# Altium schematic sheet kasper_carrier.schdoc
size 821 x 574 mm; Device: default841x594; Symbol: default841x594; Name: default841x594; Size: "A1"; Id: /; File: kasper_carrier; Sheet: /
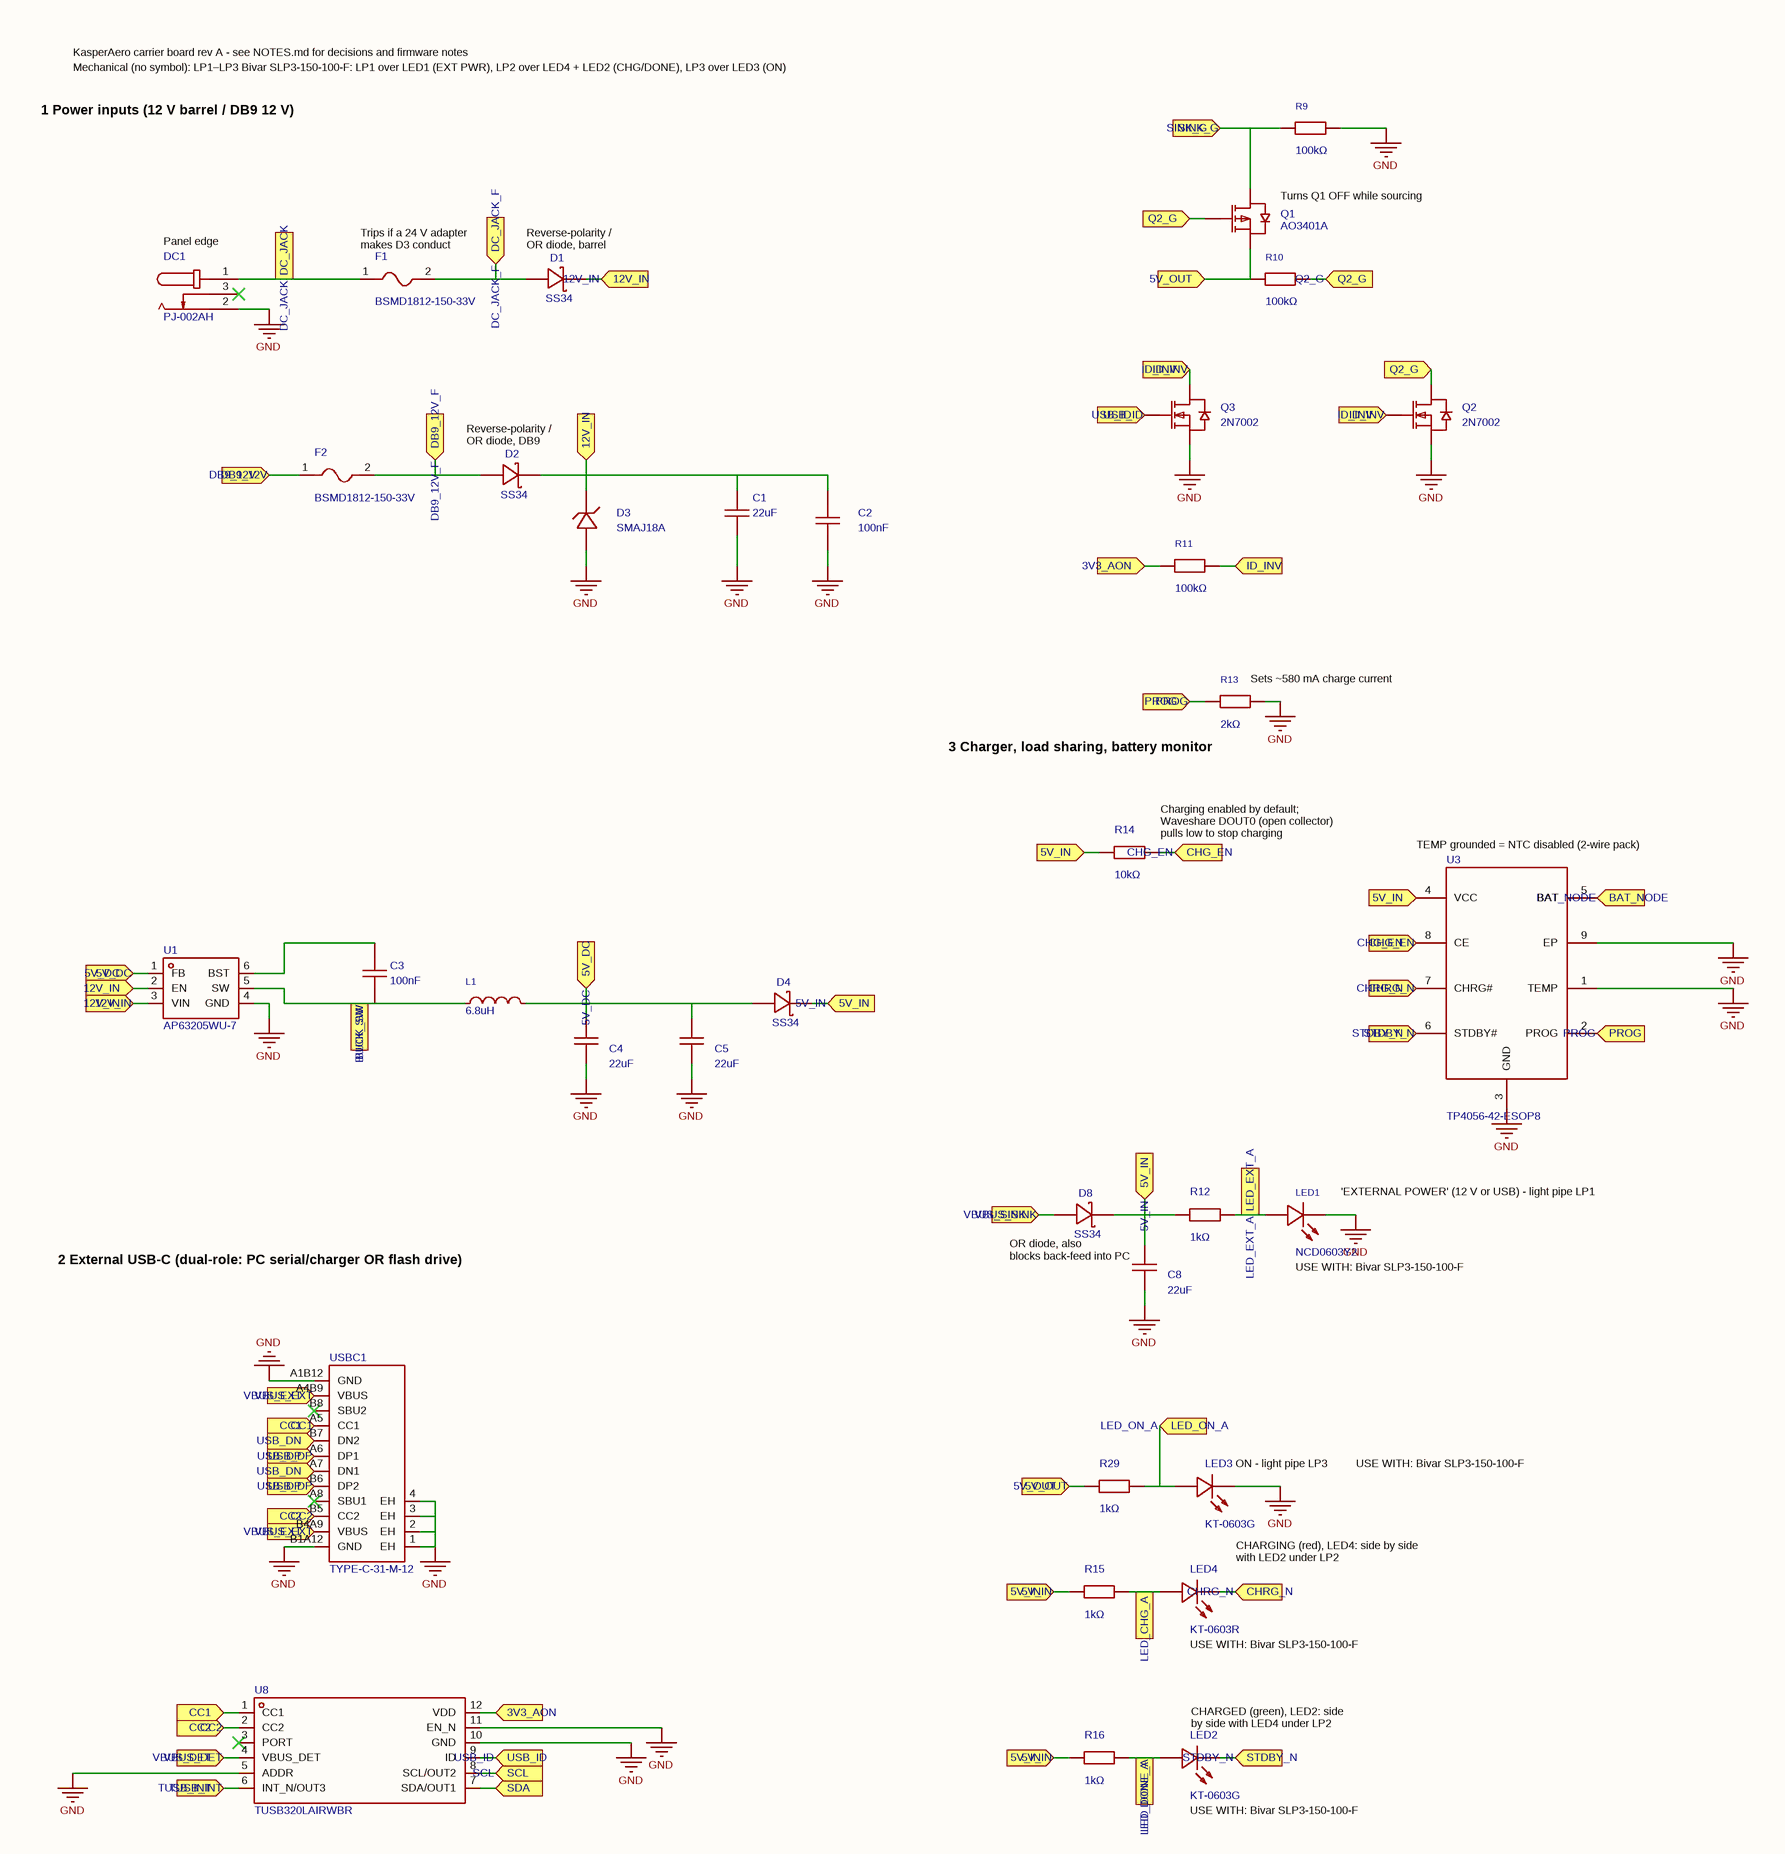
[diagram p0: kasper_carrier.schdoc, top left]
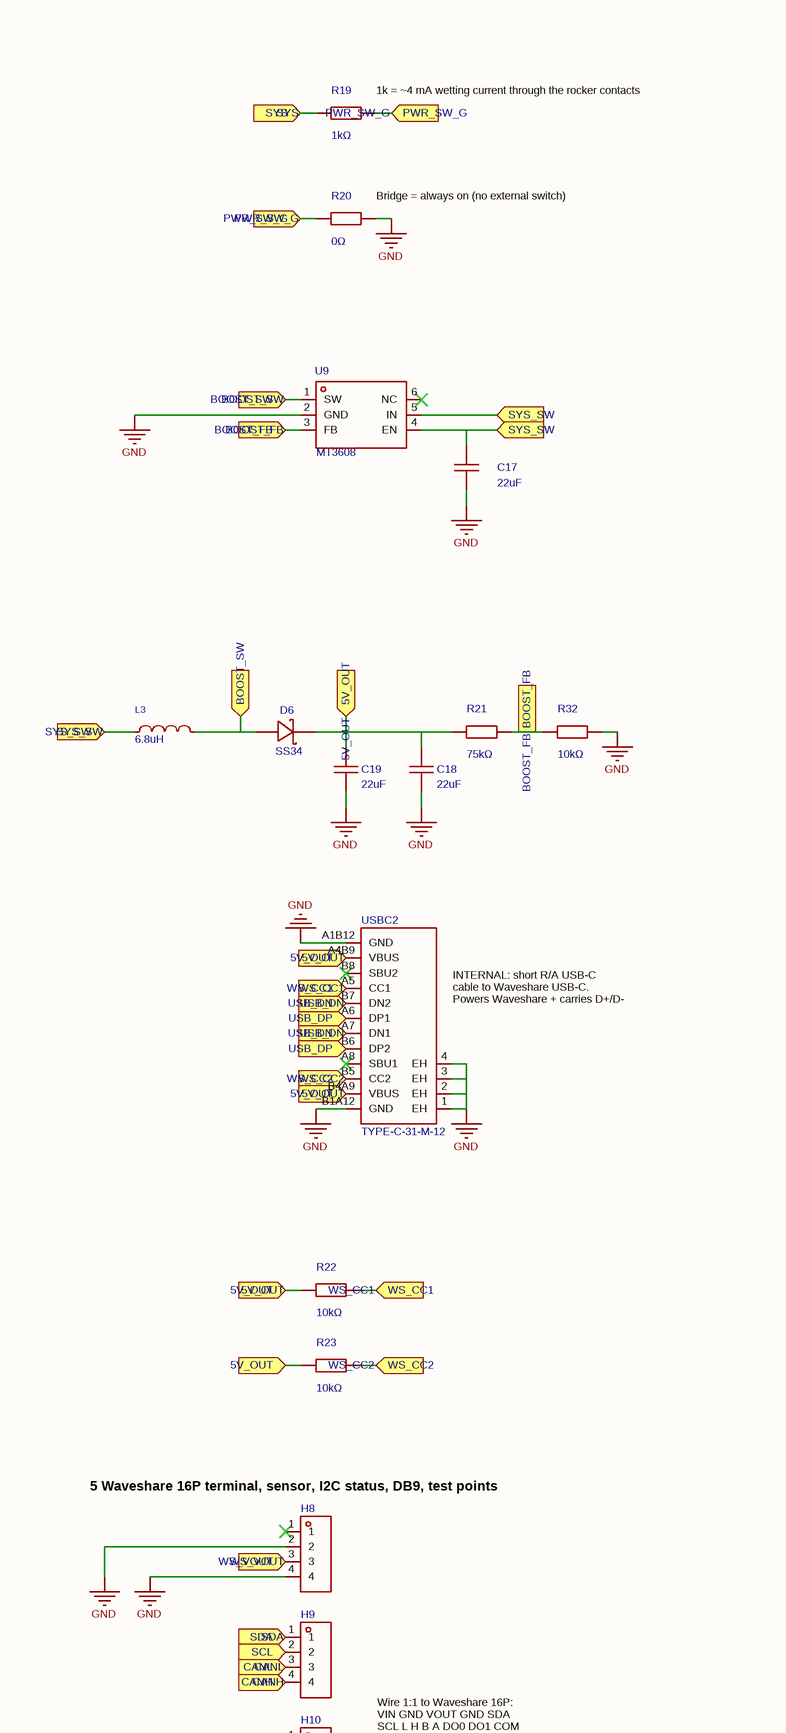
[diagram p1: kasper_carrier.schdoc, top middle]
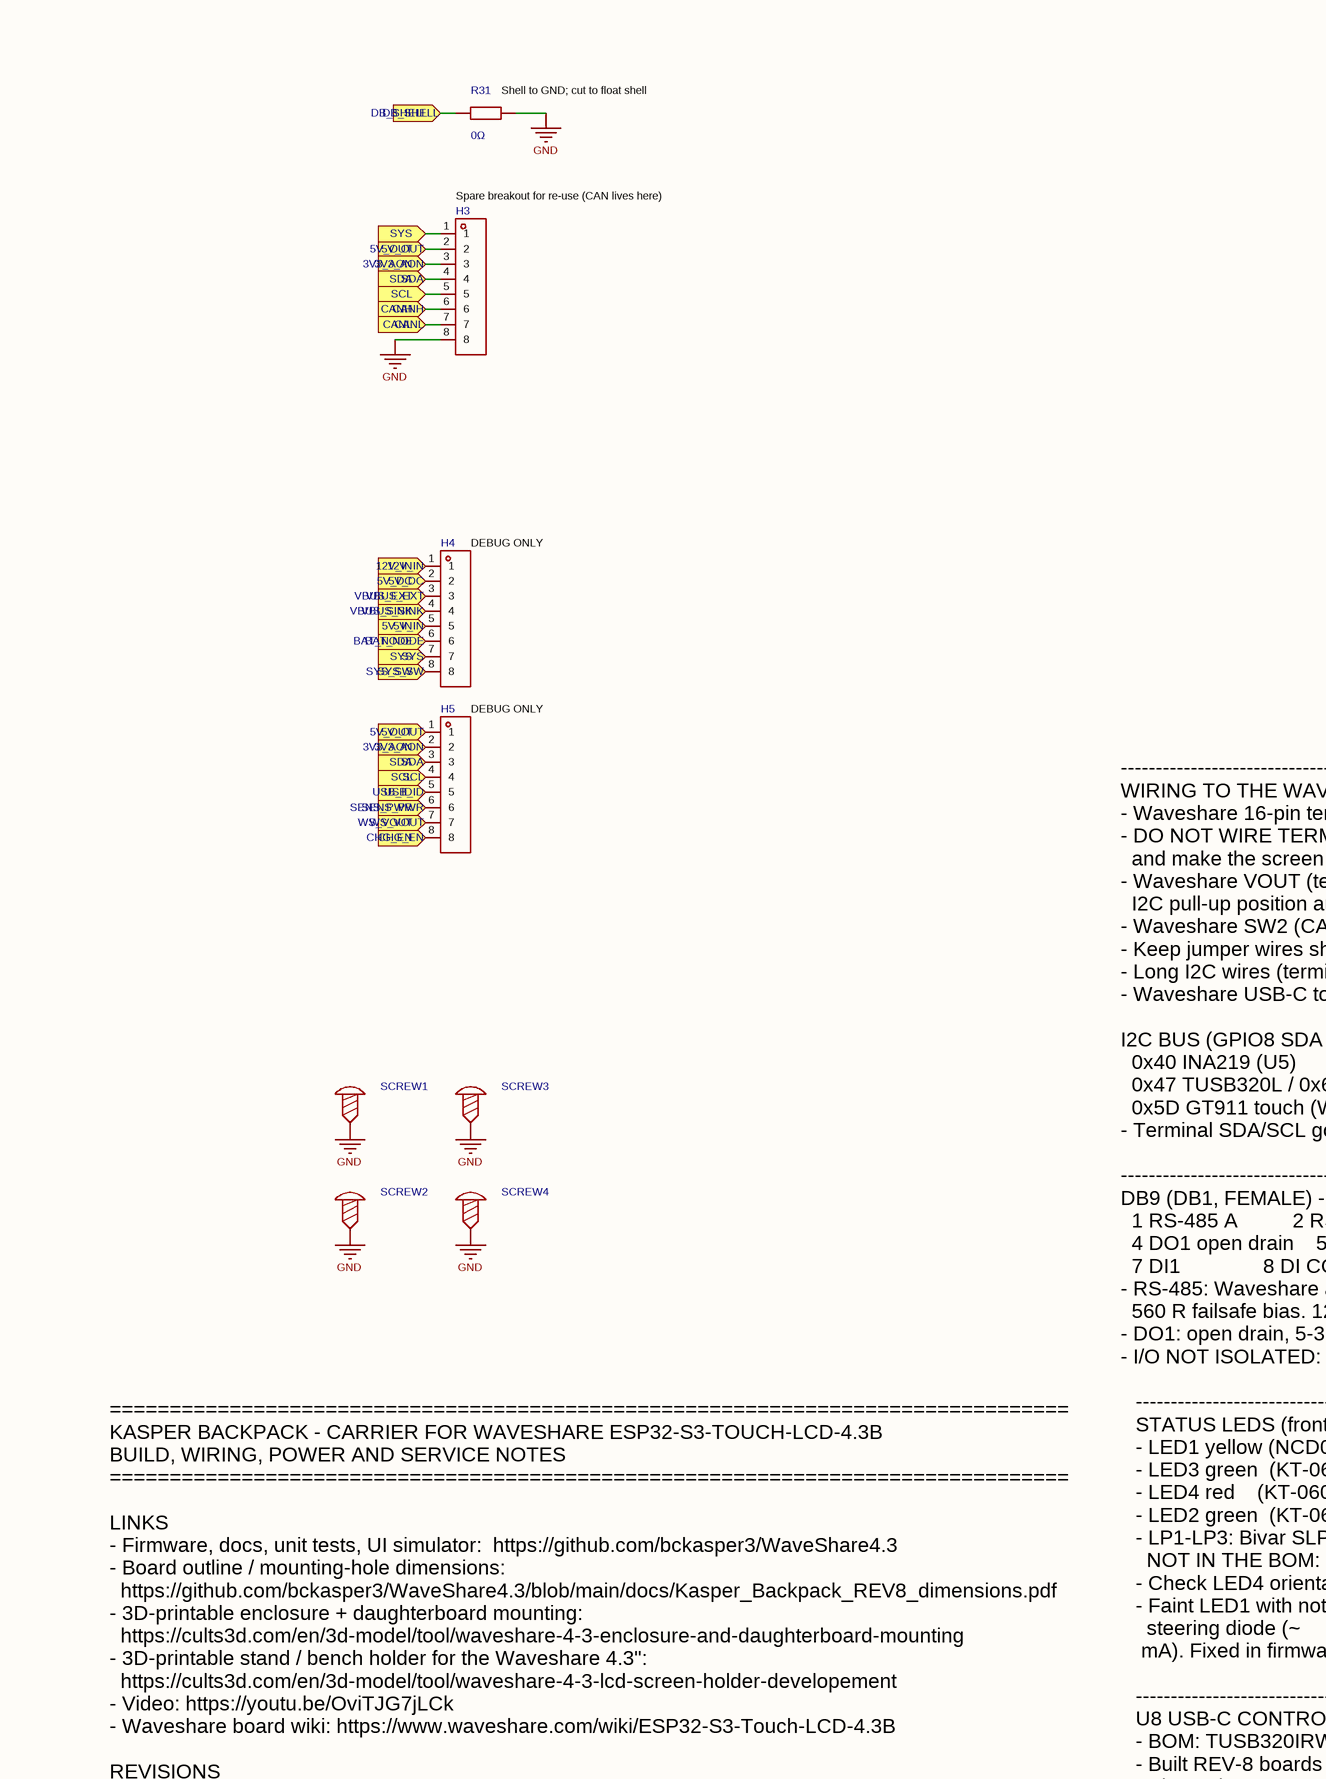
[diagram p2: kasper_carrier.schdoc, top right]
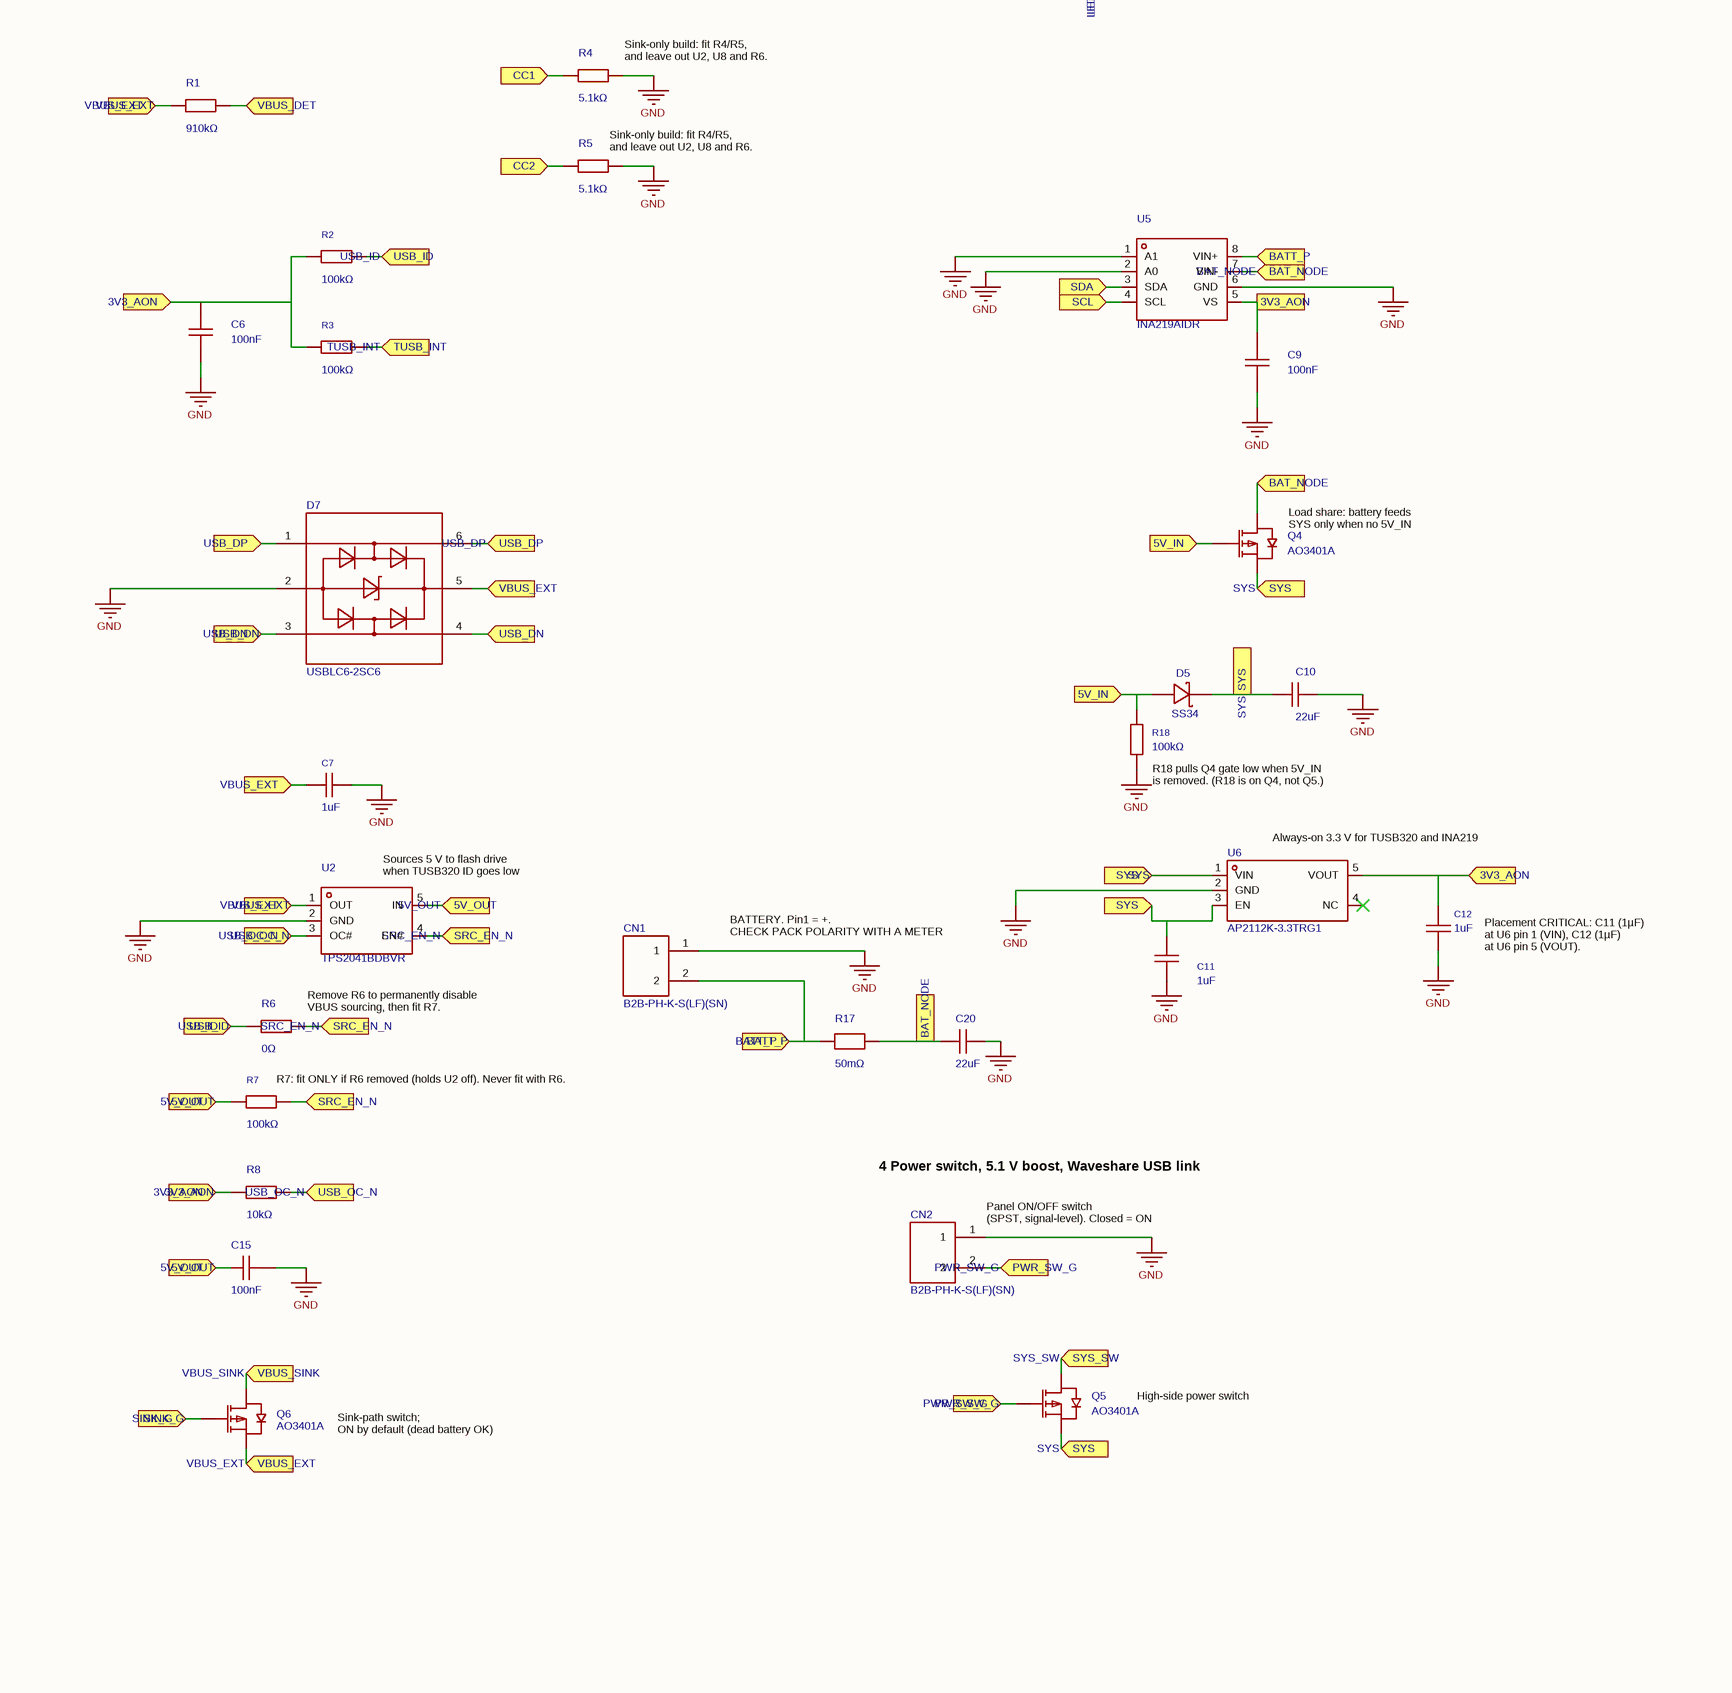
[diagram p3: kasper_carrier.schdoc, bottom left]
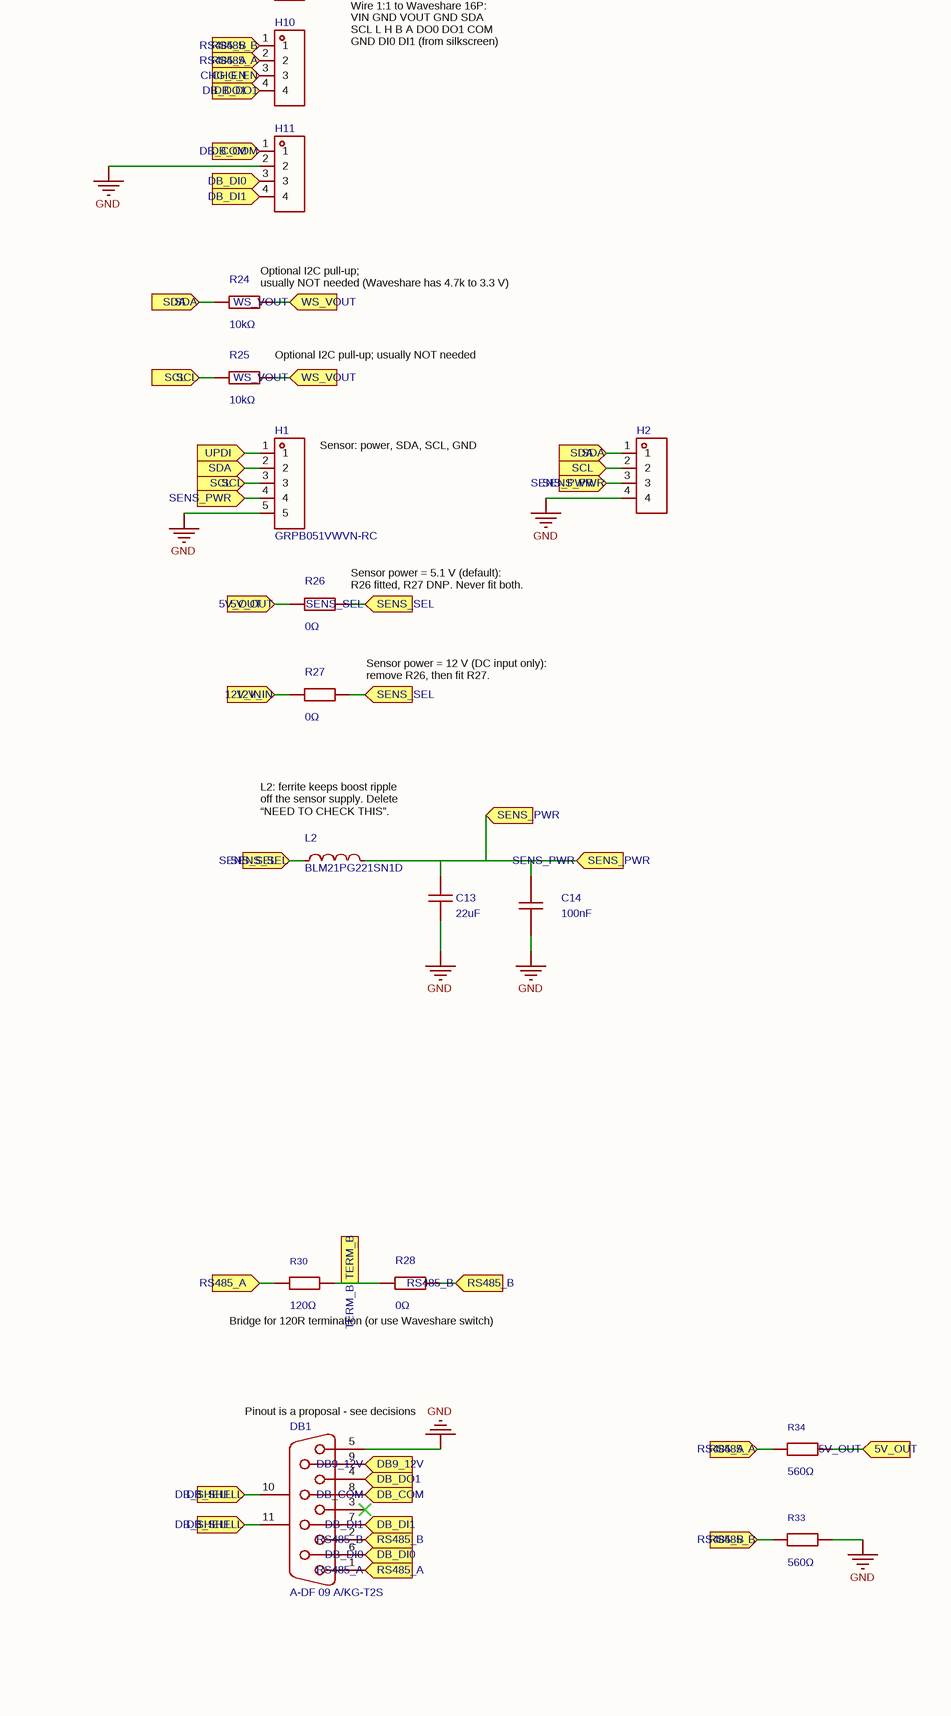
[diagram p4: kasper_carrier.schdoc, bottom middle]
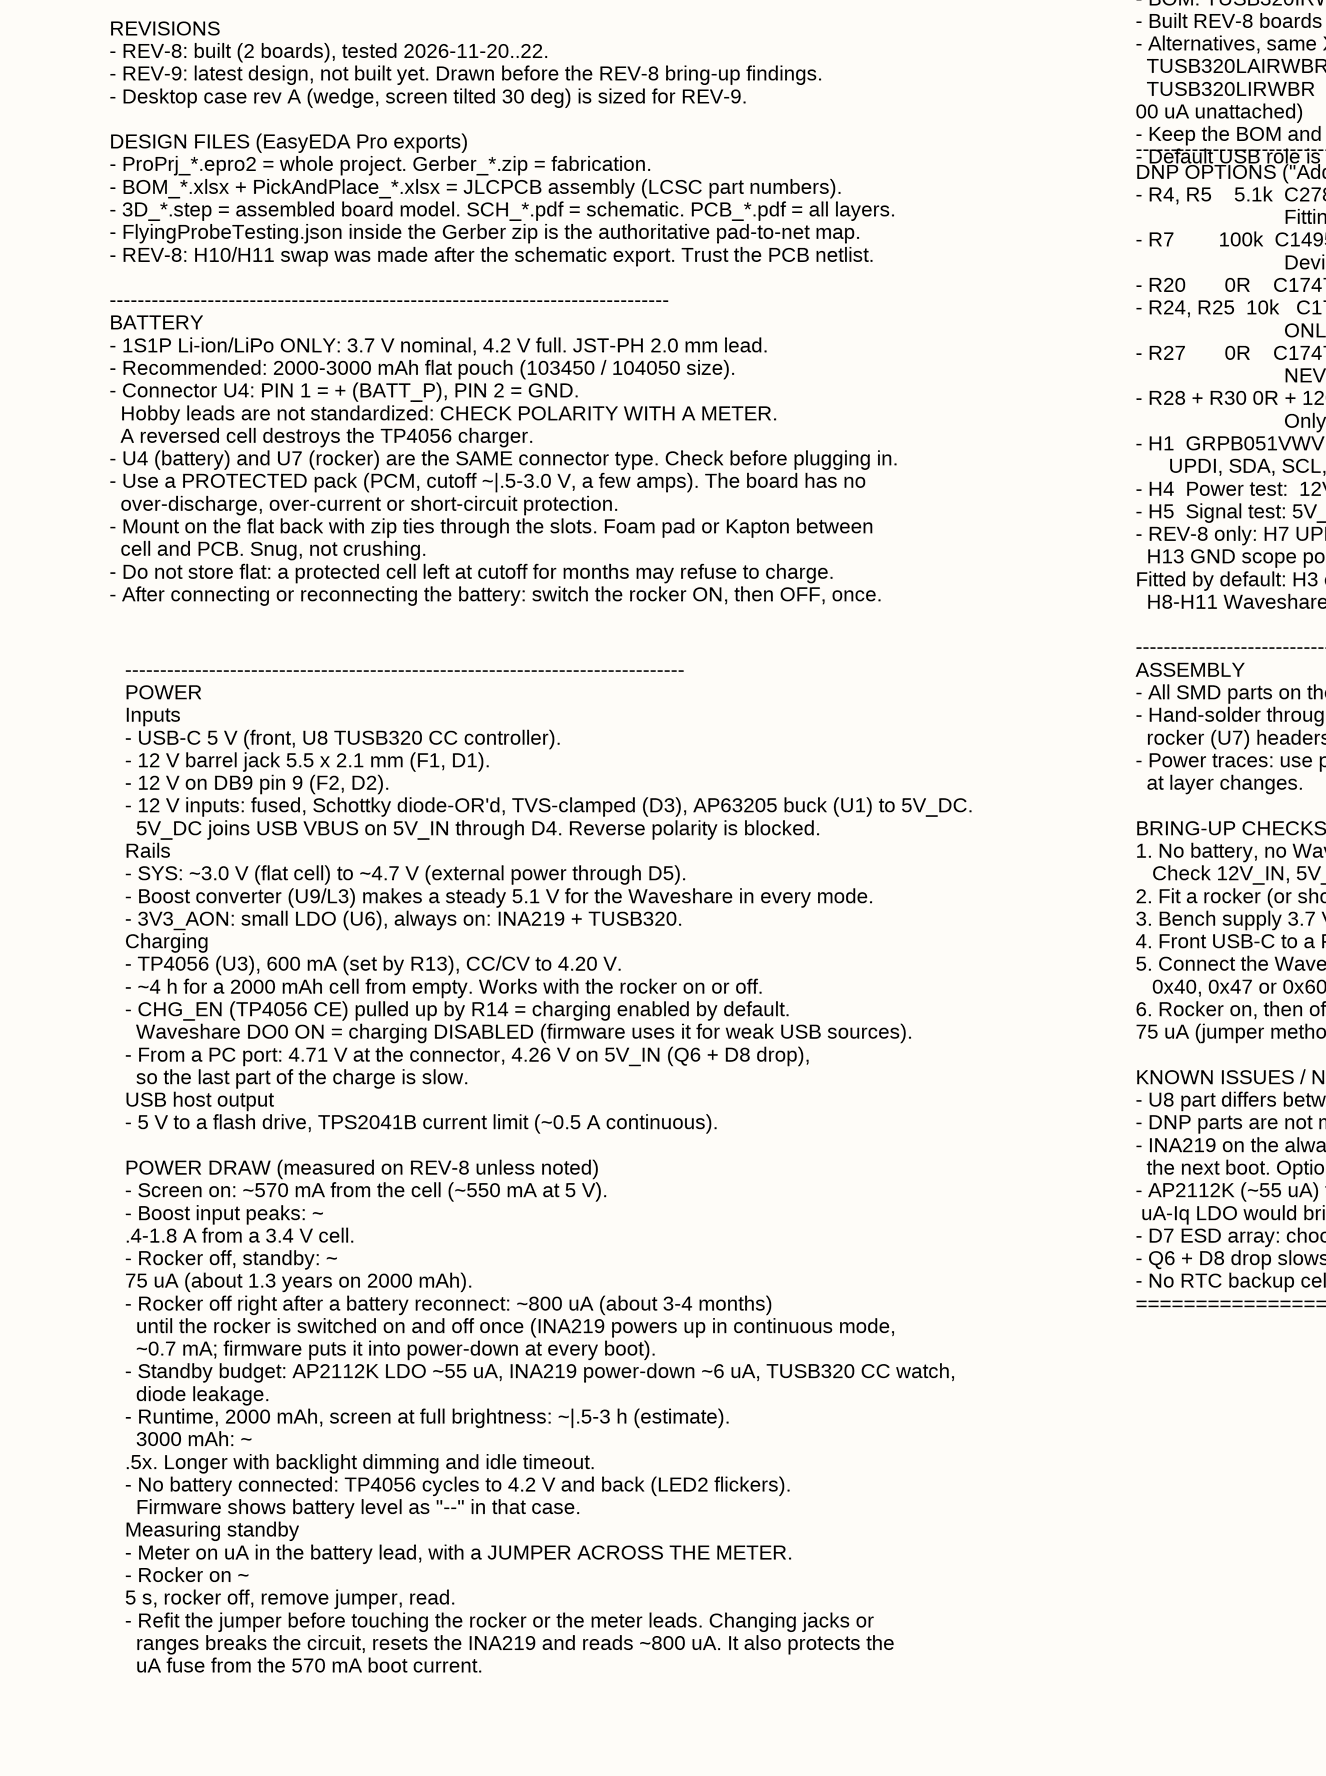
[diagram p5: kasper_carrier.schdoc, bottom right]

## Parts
C1  22uF  [C1206]
C2  100nF  [C0805]
C3  100nF  [C0805]
C4  22uF  [C1206]
C5  22uF  [C1206]
C6  100nF  [C0805]
C7  1uF  [C0805]
C8  22uF  [C1206]
C9  100nF  [C0805]
C10  22uF  [C1206]
C11  1uF  [C0805]
C12  1uF  [C0805]
C13  22uF  [C1206]
C14  100nF  [C0805]
C15  100nF  [C0805]
C17  22uF  [C1206]
C18  22uF  [C1206]
C19  22uF  [C1206]
C20  22uF  [C1206]
CN1  B2B-PH-K-S(LF)(SN)  [CONN-TH_B2B-PH-K-S]
CN2  B2B-PH-K-S(LF)(SN)  [CONN-TH_B2B-PH-K-S]
D1  SS34  [SMA_L4.3-W2.6-LS5.2-RD]
D2  SS34  [SMA_L4.3-W2.6-LS5.2-RD]
D3  SMAJ18A  [SMA_L4.4-W2.6-LS5.0-RD]
D4  SS34  [SMA_L4.3-W2.6-LS5.2-RD]
D5  SS34  [SMA_L4.3-W2.6-LS5.2-RD]
D6  SS34  [SMA_L4.3-W2.6-LS5.2-RD]
D7  USBLC6-2SC6  [SOT-23-6_L2.9-W1.6-P0.95-LS2.8-BL]
D8  SS34  [SMA_L4.3-W2.6-LS5.2-RD]
DB1  A-DF 09 A/KG-T2S  [DB9-TH_DB9F_C9900018961]
DC1  PJ-002AH  [DC-IN-TH_PJ-002AH]
F1  BSMD1812-150-33V  [F1812]
F2  BSMD1812-150-33V  [F1812]
H1  GRPB051VWVN-RC  [HDR-TH_5P-P1.27-V-M-1]
H2  (no value)  [HDR-TH_4P-P2.54-V-M]
H3  (no value)  [HDR-TH_8P-P2.54-V-F-1]
H4  (no value)  [HDR-TH_8P-P2.54-V-F-1]
H5  (no value)  [HDR-TH_8P-P2.54-V-F-1]
H8  (no value)  [HDR-TH_4P-P2.54-V-M]
H9  (no value)  [HDR-TH_4P-P2.54-V-M]
H10  (no value)  [HDR-TH_4P-P2.54-V-M]
H11  (no value)  [HDR-TH_4P-P2.54-V-M]
L1  6.8uH  [IND-SMD_L6.0-W6.0_SMNR6045]
L2  BLM21PG221SN1D  [L0805]
L3  6.8uH  [IND-SMD_L6.0-W6.0_SMNR6045]
LED1  NCD0603Y2  [LED0603-RD]
LED2  KT-0603G  [LED0603-RD]
LED3  KT-0603G  [LED0603-RD]
LED4  KT-0603R  [LED-SMD_L1.6-W0.8-R-RD]
Q1  AO3401A  [SOT-23_L2.9-W1.3-P1.90-LS2.4-BR]
Q2  2N7002  [SOT-23-3_L2.9-W1.3-P1.90-LS2.4-BR]
Q3  2N7002  [SOT-23-3_L2.9-W1.3-P1.90-LS2.4-BR]
Q4  AO3401A  [SOT-23_L2.9-W1.3-P1.90-LS2.4-BR]
Q5  AO3401A  [SOT-23_L2.9-W1.3-P1.90-LS2.4-BR]
Q6  AO3401A  [SOT-23_L2.9-W1.3-P1.90-LS2.4-BR]
R1  910kΩ  [R0805]
R2  100kΩ  [R0805]
R3  100kΩ  [R0805]
R4  5.1kΩ  [R0805]
R5  5.1kΩ  [R0805]
R6  0Ω  [R0805]
R7  100kΩ  [R0805]
R8  10kΩ  [R0805]
R9  100kΩ  [R0805]
R10  100kΩ  [R0805]
R11  100kΩ  [R0805]
R12  1kΩ  [R0805]
R13  2kΩ  [R0805]
R14  10kΩ  [R0805]
R15  1kΩ  [R0805]
R16  1kΩ  [R0805]
R17  50mΩ  [R1206]
R18  100kΩ  [R0805]
R19  1kΩ  [R0805]
R20  0Ω  [R0805]
R21  75kΩ  [R0805]
R22  10kΩ  [R0805]
R23  10kΩ  [R0805]
R24  10kΩ  [R0805]
R25  10kΩ  [R0805]
R26  0Ω  [R0805]
R27  0Ω  [R0805]
R28  0Ω  [R0805]
R29  1kΩ  [R0805]
R30  120Ω  [R0805]
R31  0Ω  [R0805]
R32  10kΩ  [R0805]
R33  560Ω  [R0805]
R34  560Ω  [R0805]
SCREW1  (no value)  [Screw-Hole-M4]
SCREW2  (no value)  [Screw-Hole-M4]
SCREW3  (no value)  [Screw-Hole-M4]
SCREW4  (no value)  [Screw-Hole-M4]
U1  AP63205WU-7  [TSOT-23-6_L2.9-W1.6-P0.95-LS2.8-BL]
U2  TPS2041BDBVR  [SOT-23-5_L3.0-W1.7-P0.95-LS2.8-BR]
U3  TP4056-42-ESOP8  [ESOP-8_L4.9-W3.9-P1.27-LS6.0-BL-EP]
U5  INA219AIDR  [SOIC-8_L4.9-W3.9-P1.27-LS6.0-BL]
U6  AP2112K-3.3TRG1  [SOT-25-5_L2.9-W1.6-P0.95-LS2.8-BL]
U8  TUSB320LAIRWBR  [X2QFN-12_L1.6-W1.6-P0.40-TL]
U9  MT3608  [SOT-23-6_L2.9-W1.6-P0.95-LS2.8-BL]
USBC1  TYPE-C-31-M-12  [USB-C_SMD-TYPE-C-31-M-12_1]
USBC2  TYPE-C-31-M-12  [USB-C_SMD-TYPE-C-31-M-12_1]

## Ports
3V3_AON (in), 5V_DC (in), 5V_IN (in), 5V_OUT (in), 12V_IN (in), BAT_NODE (in), BATT_P (in), BOOST_FB (in), BOOST_SW (in), BUCK_SW (in), CANH (in), CANL (in), CC1 (in), CC2 (in), CHG_EN (in), CHRG_N (in), DB9_12V (in), DB9_12V_F (in), DB_COM (in), DB_DI0 (in), DB_DI1 (in), DB_DO1 (in), DB_SHELL (in), DC_JACK (in), DC_JACK_F (in), ID_INV (in), LED_CHG_A (in), LED_DONE_A (in), LED_EXT_A (in), LED_ON_A (in), PROG (in), PWR_SW_G (in), Q2_G (in), RS485_A (in), RS485_B (in), SCL (in), SDA (in), SENS_PWR (in), SENS_SEL (in), SINK_G (in), SRC_EN_N (in), STDBY_N (in), SYS (in), SYS_SW (in), TERM_B (in), TUSB_INT (in), UPDI (in), USB_DN (in), USB_DP (in), USB_ID (in), USB_OC_N (in), VBUS_DET (in), VBUS_EXT (in), VBUS_SINK (in), WS_CC1 (in), WS_CC2 (in), WS_VOUT (in)

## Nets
GND: C1.1 C2.1 C4.1 C5.1 C6.1 C7.2 C8.1 C9.1 C10.1 C11.1 C12.1 C13.2 C14.1 C15.1 C17.2 C18.2 C19.2 C20.1 CN1.1 CN2.1 D3.2 D7.2 DB1.5 DC1.2 H1.5 H2.4 H3.8 H8.2 H8.4 H11.2 LED1.1(K) LED3.1(K) Q2.2(S) Q3.2(S) R4.2 R5.2 R9.2 R13.2 R18.1 R20.2 R31.2 R32.2 R33.2 SCREW1.1 SCREW2.1 SCREW3.1 SCREW4.1 U1.4(GND) U2.2(GND) U3.1(TEMP) U3.3(GND) U3.9(EP) U5.1(A1) U5.2(A0) U5.6(GND) U6.2(GND) U8.5(ADDR) U8.10(GND) U8.11(EN_N) U9.2(GND) USBC1.1(EH) USBC1.2(EH) USBC1.3(EH) USBC1.4(EH) USBC1.A1B12(GND) USBC1.B1A12(GND) USBC2.1(EH) USBC2.2(EH) USBC2.3(EH) USBC2.4(EH) USBC2.A1B12(GND) USBC2.B1A12(GND)
3V3_AON: C6.2 C9.2 C12.2 H3.3 H5.2 R2.1 R3.1 R8.1 R11.1 U5.5(VS) U6.5(VOUT) U8.12(VDD) ; port 3V3_AON
5V_DC: C4.2 C5.2 D4.2(A) H4.2 L1.2 U1.1(FB) ; port 5V_DC
5V_IN: C8.2 D4.1(K) D5.2(A) D8.1(K) H4.5 Q4.1(G) R12.1 R14.1 R15.1 R16.1 R18.2 U3.4(VCC) ; port 5V_IN
5V_OUT: C15.2 C18.1 C19.1 D6.1(K) H3.2 H5.1 Q1.2(S) R7.1 R10.1 R21.1 R22.1 R23.1 R26.1 R29.1 R34.2 U2.5(IN) USBC2.A4B9(VBUS) USBC2.B4A9(VBUS) ; port 5V_OUT
12V_IN: C1.2 C2.2 D1.1(K) D2.1(K) D3.1 H4.1 R27.1 U1.2(EN) U1.3(VIN) ; port 12V_IN
BAT_NODE: C20.2 H4.6 Q4.3(D) R17.2 U3.5(BAT) U5.7(VIN-) ; port BAT_NODE
BATT_P: CN1.2 R17.1 U5.8(VIN+) ; port BATT_P
BOOST_FB: R21.2 R32.1 U9.3(FB) ; port BOOST_FB
BOOST_SW: D6.2(A) L3.2 U9.1(SW) ; port BOOST_SW
BUCK_SW: C3.1 L1.1 U1.5(SW) ; port BUCK_SW
CANH: H3.6 H9.4 ; port CANH
CANL: H3.7 H9.3 ; port CANL
CC1: R4.1 U8.1(CC1) USBC1.A5(CC1) ; port CC1
CC2: R5.1 U8.2(CC2) USBC1.B5(CC2) ; port CC2
CHG_EN: H5.8 H10.3 R14.2 U3.8(CE) ; port CHG_EN
CHRG_N: LED4.2(K) U3.7(CHRG#) ; port CHRG_N
DB9_12V: DB1.9 F2.1 ; port DB9_12V
DB9_12V_F: D2.2(A) F2.2 ; port DB9_12V_F
DB_COM: DB1.8 H11.1 ; port DB_COM
DB_DI0: DB1.6 H11.3 ; port DB_DI0
DB_DI1: DB1.7 H11.4 ; port DB_DI1
DB_DO1: DB1.4 H10.4 ; port DB_DO1
DB_SHELL: DB1.10(MH1) DB1.11(MH2) R31.1 ; port DB_SHELL
DC_JACK: DC1.1 F1.1 ; port DC_JACK
DC_JACK_F: D1.2(A) F1.2 ; port DC_JACK_F
ID_INV: Q2.1(G) Q3.3(D) R11.2 ; port ID_INV
LED_CHG_A: LED4.1(A) R15.2 ; port LED_CHG_A
LED_DONE_A: LED2.2(A) R16.2 ; port LED_DONE_A
LED_EXT_A: LED1.2(A) R12.2 ; port LED_EXT_A
LED_ON_A: LED3.2(A) R29.2 ; port LED_ON_A
PROG: R13.1 U3.2(PROG) ; port PROG
PWR_SW_G: CN2.2 Q5.1(G) R19.2 R20.1 ; port PWR_SW_G
Q2_G: Q1.1(G) Q2.3(D) R10.2 ; port Q2_G
RS485_A: DB1.1 H10.2 R30.1 R34.1 ; port RS485_A
RS485_B: DB1.2 H10.1 R28.2 R33.1 ; port RS485_B
SCL: H1.3 H2.2 H3.5 H5.4 H9.2 R25.1 U5.4(SCL) U8.8(SCL/OUT2) ; port SCL
SDA: H1.2 H2.1 H3.4 H5.3 H9.1 R24.1 U5.3(SDA) U8.7(SDA/OUT1) ; port SDA
SENS_PWR: C13.1 C14.2 H1.4 H2.3 H5.6 L2.2 ; port SENS_PWR
SENS_SEL: L2.1 R26.2 R27.2 ; port SENS_SEL
SINK_G: Q1.3(D) Q6.1(G) R9.1 ; port SINK_G
SRC_EN_N: R6.2 R7.2 U2.4(EN#) ; port SRC_EN_N
STDBY_N: LED2.1(K) U3.6(STDBY#) ; port STDBY_N
SYS: C10.2 C11.2 D5.1(K) H3.1 H4.7 Q4.2(S) Q5.2(S) R19.1 U6.1(VIN) U6.3(EN) ; port SYS
SYS_SW: C17.1 H4.8 L3.1 Q5.3(D) U9.4(EN) U9.5(IN) ; port SYS_SW
TERM_B: R28.1 R30.2 ; port TERM_B
TUSB_INT: R3.2 U8.6(INT_N/OUT3) ; port TUSB_INT
UPDI: H1.1 ; port UPDI
USB_DN: D7.3 D7.4 USBC1.A7(DN1) USBC1.B7(DN2) USBC2.A7(DN1) USBC2.B7(DN2) ; port USB_DN
USB_DP: D7.1 D7.6 USBC1.A6(DP1) USBC1.B6(DP2) USBC2.A6(DP1) USBC2.B6(DP2) ; port USB_DP
USB_ID: H5.5 Q3.1(G) R2.2 R6.1 U8.9(ID) ; port USB_ID
USB_OC_N: R8.2 U2.3(OC#) ; port USB_OC_N
VBUS_DET: R1.2 U8.4(VBUS_DET) ; port VBUS_DET
VBUS_EXT: C7.1 D7.5 H4.3 Q6.2(S) R1.1 U2.1(OUT) USBC1.A4B9(VBUS) USBC1.B4A9(VBUS) ; port VBUS_EXT
VBUS_SINK: D8.2(A) H4.4 Q6.3(D) ; port VBUS_SINK
WS_CC1: R22.2 USBC2.A5(CC1) ; port WS_CC1
WS_CC2: R23.2 USBC2.B5(CC2) ; port WS_CC2
WS_VOUT: H5.7 H8.3 R24.2 R25.2 ; port WS_VOUT
NetC3_2: C3.2 U1.6(BST)

Not connected (* = marked no-connect by the designer): DB1 3*; DC1 3*; H8 1*; U6 4(NC)*; U8 3(PORT)*; U9 6(NC)*; USBC1 A8(SBU1)* B8(SBU2)*; USBC2 A8(SBU1)* B8(SBU2)*

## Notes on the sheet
- 1 Power inputs (12 V barrel / DB9 12 V)
- KasperAero carrier board rev A - see NOTES.md for decisions and firmware notes
- Mechanical (no symbol): LP1–LP3 Bivar SLP3-150-100-F: LP1 over LED1 (EXT PWR), LP2 over LED4 + LED2 (CHG/DONE), LP3 over LED3 (ON)
- (near R19) 1k = ~4 mA wetting current through the rocker contacts
- (near R31) Shell to GND; cut to float shell
- (near DC1) Panel edge
- (near F1) Trips if a 24 V adapter
  makes D3 conduct
- (near D1) Reverse-polarity /
  OR diode, barrel
- (near Q1) Turns Q1 OFF while sourcing
- (near R20) Bridge = always on (no external switch)
- (near H3) Spare breakout for re-use (CAN lives here)
- Reverse-polarity /
  OR diode, DB9
- (near H4) DEBUG ONLY
- (near R13) Sets ~580 mA charge current
- DEBUG ONLY
- (near R13) 3 Charger, load sharing, battery monitor
- --------------------------------------------------------------------------------
  WIRING TO THE WAVESHARE
  - Waveshare 16-pin terminal to carrier headers H8-H11, pin for pin.
  - DO NOT WIRE TERMINAL PINS 7 AND 8 (CAN L / CAN H). They couple noise onto I2C
  and make the screen blink. Do not use H3's CAN pins with them connected either.
  - Waveshare VOUT (terminal pin 3) = 3.3 V. Measure H8-3. Never 5 V: it feeds the
  I2C pull-up position and would over-drive the TUSB320 (rated 3.6 V).
  - Waveshare SW2 (CAN / RS-485 120 R termination) = OFF (factory default).
  - Keep jumper wires short and away from the boost converter (L3/U9).
  - Long I2C wires (terminal 5/6): twist each with a ground wire.
  - Waveshare USB-C to the ESP32 (D+/D- on GPIO19/20). Flash firmware through it.
  I2C BUS (GPIO8 SDA / GPIO9 SCL, shared, 3.3 V)
  0x40 INA219 (U5)              0x41 TMR probe ADS122C04 (A0 to DVDD)
  0x47 TUSB320L / 0x60 TUSB320  0x51 PCF85063 RTC (Waveshare)
  0x5D GT911 touch (Waveshare)  0x20-0x27, 0x30-0x3F CH422G expander (Waveshare)
  - Terminal SDA/SCL go through a MOSFET level shifter, 4.7k to VOUT.
  --------------------------------------------------------------------------------
  DB9 (DB1, FEMALE) - NOT RS-232
  1 RS-485 A          2 RS-485 B          3 NC
  4 DO1 open drain    5 GND               6 DI0
  7 DI1               8 DI COM            9 +12 V INPUT
  - RS-485: Waveshare auto-direction transceiver (UART0, GPIO43/44), Modbus RTU slave.
  560 R failsafe bias. 120 R termination is DNP (R28 + R30).
  - DO1: open drain, 5-36 V, 450 mA. DI0/DI1: Waveshare optocoupled inputs.
  - I/O NOT ISOLATED: Waveshare I/O ground is tied to board GND at H11-2.
- (near R14) Charging enabled by default;
  Waveshare DOUT0 (open collector)
  pulls low to stop charging
- (near U3) TEMP grounded = NTC disabled (2-wire pack)
- (near USBC2) INTERNAL: short R/A USB-C
  cable to Waveshare USB-C.
  Powers Waveshare + carries D+/D-
- (near C8) OR diode, also
  blocks back-feed into PC
- (near LED1) 'EXTERNAL POWER' (12 V or USB) - light pipe LP1
- 2 External USB-C (dual-role: PC serial/charger OR flash drive)
- (near LED1) USE WITH: Bivar SLP3-150-100-F
- --------------------------------------------------------------------------------
  STATUS LEDS (front light pipes)
  - LED1 yellow (NCD0603Y2)  = external power present   -> LP1
  - LED3 green  (KT-0603G)   = rocker on, powered       -> LP3
  - LED4 red    (KT-0603R)   = charging                 -> LP2
  - LED2 green  (KT-0603G)   = charge complete          -> LP2
  - LP1-LP3: Bivar SLP3-150-100-F (3 mm, flat lens, right-angle, press-fit).
  NOT IN THE BOM: order separately, fit by hand.
  - Check LED4 orientation against the cathode mark during assembly.
  - Faint LED1 with nothing plugged in = ESP32 D+ pull-up leaking through D7's VBUS
  steering diode (~
  mA). Fixed in firmware (pull-up only while a cable is attached).
  --------------------------------------------------------------------------------
  U8 USB-C CONTROLLER
  - BOM: TUSB320IRWBR (C80170, I2C 0x60).
  - Built REV-8 boards have a TUSB320L (I2C 0x47). Firmware accepts both.
  - Alternatives, same X2QFN-12 1.6x1.6 footprint:
  TUSB320LAIRWBR (C132554, newer, ~70 uA unattached)
  TUSB320LIRWBR  (C2836598, ~
  00 uA unattached)
  - Keep the BOM and the assembly order in agreement.
  - Default USB role is device (PC). Host (flash drive) only when U8 reports a drive.
- (near LED3) ON - light pipe LP3
- USE WITH: Bivar SLP3-150-100-F
- CHARGING (red), LED4: side by side
  with LED2 under LP2
- (near H8) 5 Waveshare 16P terminal, sensor, I2C status, DB9, test points
- (near LED2) CHARGED (green), LED2: side
  by side with LED4 under LP2
- (near LED4) USE WITH: Bivar SLP3-150-100-F
- Wire 1:1 to Waveshare 16P:
  VIN GND VOUT GND SDA
  SCL L H B A DO0 DO1 COM
  GND DI0 DI1 (from silkscreen)
- Sink-only build: fit R4/R5,
  and leave out U2, U8 and R6.
- (near LED2) USE WITH: Bivar SLP3-150-100-F
- --------------------------------------------------------------------------------
  DNP OPTIONS ("Add into BOM" = no)
  - R4, R5    5.1k  C27834   CC1/CC2 to GND. ONLY if U8 is NOT fitted.
  Fitting them breaks flash-drive export.
  - R7        100k  C149504  5V_OUT to SRC_EN_N: holds TPS2041B off, no host mode.
  Device-only builds. NEVER WITH R6.
  - R20       0R    C17477   PWR_SW_G to GND: bypasses the rocker, always on.
  - R24, R25  10k   C17414   Extra I2C pull-ups to WS_VOUT. Long leads / slow edges.
  ONLY WITH VOUT = 3.3 V.
  - R27       0R    C17477   12V_IN to SENS_SEL: sensor powered from 12 V, not 5 V.
  NEVER WITH R26.
  - R28 + R30 0R + 120R      RS-485 termination, in series through TERM_B.
  Only if this unit is always at the physical end of the bus.
  - H1  GRPB051VWVN-RC (C5447632, 1.27 mm): sensor daughterboard.
  UPDI, SDA, SCL, SENS_PWR, GND. Hand-fit.
  - H4  Power test:  12V_IN, 5V_DC, VBUS_EXT, VBUS_SINK, 5V_IN, BAT_NODE, SYS, SYS_SW
  - H5  Signal test: 5V_OUT, 3V3_AON, SDA, SCL, USB_ID, SENS_PWR, WS_VOUT, CHG_EN
  - REV-8 only: H7 UPDI (program the sensor AVR), H12 SENS_PWR test point,
  H13 GND scope point.
  Fitted by default: H3 expansion (SYS, 5V_OUT, 3V3_AON, SDA, SCL, CANH, CANL, GND),
  H8-H11 Waveshare terminal headers, R6, R26.
  --------------------------------------------------------------------------------
  ASSEMBLY
  - All SMD parts on the top side. Back is flat for the battery.
  - Hand-solder through-hole: DB9 (DB1), barrel jack, JST-PH battery (U4) and
  rocker (U7) headers, light pipes, any optional headers.
  - Power traces: use pours for anything over ~300 mA, several vias per amp
  at layer changes.
  BRING-UP CHECKS
  1. No battery, no Waveshare. 12 V on the barrel jack, supply limited to 200 mA.
  Check 12V_IN, 5V_DC, 5V_IN on H4. LED1 lights.
  2. Fit a rocker (or short U7). Check SYS_SW on H4, 5V_OUT = 5.1 V on H5. LED3 lights.
  3. Bench supply 3.7 V / 1 A limit on U4 (pin 1 = +). Charge current flows, LED4 lights.
  4. Front USB-C to a PC: charges. Flash drive in: 5 V on VBUS.
  5. Connect the Waveshare (no CAN L/H), flash firmware, I2C scan:
  0x40, 0x47 or 0x60, 0x51, 0x5D, CH422G (plus 0x41 with the probe).
  6. Rocker on, then off. Standby ~
  75 uA (jumper method above).
  KNOWN ISSUES / NEXT REVISION
  - U8 part differs between BOM and built boards (see above).
  - DNP parts are not marked "DNP" on the schematic (hidden BOM flag only).
  - INA219 on the always-on rail: a battery reconnect leaves ~800 uA standby until
  the next boot. Option: move it to the switched rail.
  - AP2112K (~55 uA) for 3V3_AON: a ~
  uA-Iq LDO would bring standby to ~50-100 uA.
  - D7 ESD array: choose one without a VBUS rail.
  - Q6 + D8 drop slows the end of charge from a PC port: consider an ideal diode.
  - No RTC backup cell on the Waveshare as built: the clock resets with power.
  ================================================================================
- (near R5) Sink-only build: fit R4/R5,
  and leave out U2, U8 and R6.
- Optional I2C pull-up;
  usually NOT needed (Waveshare has 4.7k to 3.3 V)
- (near R25) Optional I2C pull-up; usually NOT needed
- (near H1) Sensor: power, SDA, SCL, GND
- Sensor power = 5.1 V (default):
  R26 fitted, R27 DNP. Never fit both.
- (near C10) Load share: battery feeds
  SYS only when no 5V_IN
- Sensor power = 12 V (DC input only):
  remove R26, then fit R27.
- --------------------------------------------------------------------------------
  POWER
  Inputs
  - USB-C 5 V (front, U8 TUSB320 CC controller).
  - 12 V barrel jack 5.5 x 2.1 mm (F1, D1).
  - 12 V on DB9 pin 9 (F2, D2).
  - 12 V inputs: fused, Schottky diode-OR'd, TVS-clamped (D3), AP63205 buck (U1) to 5V_DC.
  5V_DC joins USB VBUS on 5V_IN through D4. Reverse polarity is blocked.
  Rails
  - SYS: ~3.0 V (flat cell) to ~4.7 V (external power through D5).
  - Boost converter (U9/L3) makes a steady 5.1 V for the Waveshare in every mode.
  - 3V3_AON: small LDO (U6), always on: INA219 + TUSB320.
  Charging
  - TP4056 (U3), 600 mA (set by R13), CC/CV to 4.20 V.
  - ~4 h for a 2000 mAh cell from empty. Works with the rocker on or off.
  - CHG_EN (TP4056 CE) pulled up by R14 = charging enabled by default.
  Waveshare DO0 ON = charging DISABLED (firmware uses it for weak USB sources).
  - From a PC port: 4.71 V at the connector, 4.26 V on 5V_IN (Q6 + D8 drop),
  so the last part of the charge is slow.
  USB host output
  - 5 V to a flash drive, TPS2041B current limit (~0.5 A continuous).
  POWER DRAW (measured on REV-8 unless noted)
  - Screen on: ~570 mA from the cell (~550 mA at 5 V).
  - Boost input peaks: ~
  .4-1.8 A from a 3.4 V cell.
  - Rocker off, standby: ~
  75 uA (about 1.3 years on 2000 mAh).
  - Rocker off right after a battery reconnect: ~800 uA (about 3-4 months)
  until the rocker is switched on and off once (INA219 powers up in continuous mode,
  ~0.7 mA; firmware puts it into power-down at every boot).
  - Standby budget: AP2112K LDO ~55 uA, INA219 power-down ~6 uA, TUSB320 CC watch,
  diode leakage.
  - Runtime, 2000 mAh, screen at full brightness: ~|.5-3 h (estimate).
  3000 mAh: ~
  .5x. Longer with backlight dimming and idle timeout.
  - No battery connected: TP4056 cycles to 4.2 V and back (LED2 flickers).
  Firmware shows battery level as "--" in that case.
  Measuring standby
  - Meter on uA in the battery lead, with a JUMPER ACROSS THE METER.
  - Rocker on ~
  5 s, rocker off, remove jumper, read.
  - Refit the jumper before touching the rocker or the meter leads. Changing jacks or
  ranges breaks the circuit, resets the INA219 and reads ~800 uA. It also protects the
  uA fuse from the 570 mA boot current.
- (near L2) L2: ferrite keeps boost ripple
  off the sensor supply. Delete
  “NEED TO CHECK THIS”.
- (near U6) R18 pulls Q4 gate low when 5V_IN
  is removed. (R18 is on Q4, not Q5.)
- (near U2) Sources 5 V to flash drive
  when TUSB320 ID goes low
- (near U6) Always-on 3.3 V for TUSB320 and INA219
- (near R17) BATTERY. Pin1 = +.
  CHECK PACK POLARITY WITH A METER
- (near C12) Placement CRITICAL: C11 (1µF)
  at U6 pin 1 (VIN), C12 (1µF)
  at U6 pin 5 (VOUT).
- (near R6) Remove R6 to permanently disable
  VBUS sourcing, then fit R7.
- (near R7) R7: fit ONLY if R6 removed (holds U2 off). Never fit with R6.
- 4 Power switch, 5.1 V boost, Waveshare USB link
- (near Q5) Panel ON/OFF switch
  (SPST, signal-level). Closed = ON
- Bridge for 120R termination (or use Waveshare switch)
- (near DB1) Pinout is a proposal - see decisions
- Sink-path switch;
  ON by default (dead battery OK)
- High-side power switch

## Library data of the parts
C1 C4 C5 C8 C10 C13 C17-C20 = CL31A226KAHNNNE: Capacitance:22uF Tolerance:±10% Tolerance:±10% Voltage Rating:25V Temperature Coefficient:X5R; Manufacturer: SAMSUNG(三星); AddInBom: yes; ModelId: c6790e9475e1483991d2c64340b24e960819f05c4eef4c71ace90d822a990e87; ModelName: C1206_L3.2-W1.6-H1.3; ModelTransform: 125.984,62.992,0,0,0,0,0,0,0; Tolerance: ±10%; Voltage Rating: 25V; Temperature Coefficient: X5R
C2 C3 C6 C9 C14 C15 = CC0805KRX7R9BB104: Capacitance:100nF Tolerance:±10% Tolerance:±10% Voltage Rating:50V Temperature Coefficient:X7R; Manufacturer: YAGEO(国巨); AddInBom: yes; ModelId: 8c88e81f49c6409b980720ec8953afb60819f05c4eef4c71ace90d822a990e87; ModelName: C0805_L2.0-W1.3-H1.3; ModelTransform: 78.74,51.181,0,0,0,0,0,0.0005,0; Tolerance: ±10%; Voltage Rating: 50V; Temperature Coefficient: X7R
C7 C11 C12 = CL21B105KBFNNNE: Capacitance:1uF Tolerance:±10% Tolerance:±10% Voltage Rating:50V Temperature Coefficient:X7R; Manufacturer: SAMSUNG(三星); AddInBom: yes; ModelId: 8c88e81f49c6409b980720ec8953afb60819f05c4eef4c71ace90d822a990e87; ModelName: C0805_L2.0-W1.3-H1.3; ModelTransform: 78.74,51.181,0,0,0,0,0,0.0005,0; Tolerance: ±10%; Voltage Rating: 50V; Temperature Coefficient: X7R
CN1 CN2 = B2B-PH-K-S(LF)(SN): Pins Structure:1x2P Pitch:2mm Mounting Type:Through Hole Reference Series:PH Number of Pins:2P Number of Rows:1 Number of PINs Per Row:2 Row Spacing:- Current Rating:2A Contact Material:Brass Contact Plating:Tin Operating Temperature:-25℃~+85℃ Operating T; Manufacturer: JST; AddInBom: yes; ModelId: 5cc63648eb1041ff813a836ee0942c910819f05c4eef4c71ace90d822a990e87; ModelName: CONN-TH_PH2.00-LI-2P; ModelTransform: 236.25937,181.102,0,180,0,0,0,23.622,-137.795; Pins Structure: 1x2P; Pitch: 2mm; Reference Series: PH; Number of PINs Per Row: 2; Current Rating: 2A; Voltage Rating: 100V; Plastic Material: PA66; Flame Retardant Rating: UL94V-0; Supplementary Features: K Pin; Z-Height of the Board: 6mm; X-Length of Bottom Edge on Board (Spacing Line): 5.9mm; Y-Width of Bottom Edge on Board: 4.5mm
D1 D2 D4-D6 D8 = SS34_C8678: Diode Configuration:Standalone Voltage - Forward(Vf@If):550mV@3A Voltage - DC Reverse(Vr):40V Current - Rectified:3A Reverse Leakage Current (Ir):500uA@40V Operating Junction Temperature Range:-55℃~+125℃ Operating Junction Temperature Range:-55℃~+125℃ Non; Manufacturer: MDD(辰达半导体); AddInBom: yes; ModelId: e3551acb3c5a4975a5e9d36087fe1fa20819f05c4eef4c71ace90d822a990e87; ModelTransform: 185.039,102.362,0,0,0,0,0,0,0; Voltage - DC Reverse(Vr): 40V; Current - Rectified: 3A; Non-Repetitive Peak Forward Surge Current: 80A
D3 = SMAJ18A_C148219: Polarity:Unidirectional Reverse Stand-Off Voltage (Vrwm):18V Clamping Voltage:29.2V Peak Pulse Current (Ipp):13.7A@10/1000us Peak Pulse Power Dissipation (Ppp):400W@10/1000us Voltage - Breakdown:22.1V Reverse Leakage Current (Ir):1uA Number of Channels:1; Manufacturer: Littelfuse(美国力特); AddInBom: yes; ModelId: f51095f10bda4868a97202a5ed5885410819f05c4eef4c71ace90d822a990e87; ModelTransform: 204.724,98.425,0,0,0,0,0,0,0; Reverse Stand-Off Voltage (Vrwm): 18V; Clamping Voltage: 29.2V; Voltage - Breakdown: 22.1V; Reverse Leakage Current (Ir): 1uA; Number of Channels: 1; level of protection: IEC 61000-4-4；IEC 61000-4-2; Type: TVS
D7 = USBLC6-2SC6_C7519: Polarity:Unidirectional Reverse Stand-Off Voltage (Vrwm):5.25V Clamping Voltage:17V Peak Pulse Current (Ipp):5A Voltage - Breakdown:6V Reverse Leakage Current (Ir):150nA Number of Channels:2 Operating Temperature:-40℃~+125℃ Operating Temperature:-40℃~+125; Manufacturer: ST(意法半导体); AddInBom: yes; ModelId: 1370be37a17e44418ae52e2b4cc1f5e50819f05c4eef4c71ace90d822a990e87; ModelName: SOT-23-6_L2.9-W1.6-H1.5-LS2.8-P0.95; ModelTransform: 110.236,113.364,0,90,0,0,0.0005,0.0005,0; Reverse Stand-Off Voltage (Vrwm): 5.25V; Clamping Voltage: 17V; Peak Pulse Current (Ipp): 5A; Voltage - Breakdown: 6V; Reverse Leakage Current (Ir): 150nA; Number of Channels: 2; level of protection: IEC 61000-4-2; Type: ESD; Junction Capacitance: 3.5pF
DB1 = A-DF 09 A/KG-T2S: Connector Type:Standard D-Sub Gender:Female Number of Pins:9P Mounting Type:Right Angle Number of Rows:2 Current Rating-Signal:3A Color:Black Operating Temperature:-55℃~+105℃ Operating Temperature:-55℃~+105℃; Manufacturer: ASSMANN; Add into BOM: yes; ModelId: ef06ade5e717490592459d28fa0205e80819f05c4eef4c71ace90d822a990e87; ModelTransform: 1212.596,716.57341,0,0,0,0,0,-242.126,-157.48; Gender: Female; Current Rating-Signal: 3A
DC1 = PJ-002AH: Connector Type:DC Power Jack Mounting Type:Right Angle Inside Contact Diameter:2mm Outside Contact Diameter:6.5mm Current Rating:5A Voltage Rating (Max):24V Body Height:11mm Length:14.4mm Width:9mm Operating Temperature:-25℃~+85℃ Operating Temperature:-25; Manufacturer: CUI; AddInBom: yes; ModelId: a71a37d95bbe4103ad38e90fbbfda01b0819f05c4eef4c71ace90d822a990e87; ModelTransform: 566.928,370.078,0,0,0,0,137.795,-85.63,-137.795; Inside Contact Diameter: 2mm; Outside Contact Diameter: 6.5mm; Current Rating: 5A; Voltage Rating (Max): 24V; Body Height: 11mm
F1 F2 = BSMD1812-150-33V: Voltage - Max:33V Current - Max:40A Hold Current:1.5A Trip Current:3A Power Dissipation:1W Resistance - Initial (Ri) (Min):40mΩ Resistance - Post Trip (R1) (Max):160mΩ Time to Trip(Max):500ms Operating Temperature:-40℃~+85℃ Operating Temperature:-40℃~+85℃; Manufacturer: BHFUSE(佰宏); AddInBom: yes; ModelId: 2c21fc2ee1444accbf1837c83de544380819f05c4eef4c71ace90d822a990e87; ModelName: F1812_L4.5-W3.2-H1.0; ModelTransform: 177.165,125.984,0,0,0,0,0.0005,0,0; Voltage - Max: 33V; Current - Max: 40A; Hold Current: 1.5A; Trip Current: 3A; Power Dissipation: 1W; Resistance - Initial (Ri) (Min): 40mΩ; Resistance - Post Trip (R1) (Max): 160mΩ; Time to Trip(Max): 500ms
H1 = GRPB051VWVN-RC: Pitch:1.27mm Mounting Type:Through Hole Number of Rows:1 Number of Pins:5P Current Rating:1A Contact Material:Brass Contact Plating:Gold Operating Temperature:-40℃~+105℃ Operating Temperature:-40℃~+105℃; Manufacturer: Sullins; Add into BOM: no; 3D Model: 510879fb8d8e4b26bf5df066f1e644c7; 3D Model Transform: 250.393,94.488,0,0,0,0,0,0,-98.425; Pitch: 1.27mm; Current Rating: 1A; ConvertToPcb: yes
H2 = HDR-M_2.54_1x4P: Symbol: PZ254V-11-04P; 3D Model: 69e0934d9b9245f6ab499bc5a319b3aa0819f05c4eef4c71ace90d822a990e87; 3D Model Transform: 399.999,104.7242,0,0,0,0,0,0,-118.11; Add into BOM: no; ConvertToPcb: yes; ModelName: HDR-TH_4P-P2.54-M-LI-1X4P
H3 = HDR-F_2.54_1x8P: Symbol: Header-Female-2.54_1x8; Add into BOM: yes; ModelId: 3a4a5f772e574dcd891b9f6604ec8e180819f05c4eef4c71ace90d822a990e87; ModelName: HDR-F-2.54_1x8; ModelTransform: 799.99844,100,0,0,0,0,0,0,-118.11
H4 H5 = HDR-F_2.54_1x8P: Symbol: Header-Female-2.54_1x8; Add into BOM: no; ConvertToPcb: yes; ModelId: 3a4a5f772e574dcd891b9f6604ec8e180819f05c4eef4c71ace90d822a990e87; ModelName: HDR-F-2.54_1x8; ModelTransform: 799.99844,100,0,0,0,0,0,0,-118.11
H8-H11 = HDR-M_2.54_1x4P: Symbol: PZ254V-11-04P; ConvertToPcb: yes; ModelId: 69e0934d9b9245f6ab499bc5a319b3aa0819f05c4eef4c71ace90d822a990e87; ModelName: HDR-TH_4P-P2.54-M-LI-1X4P; ModelTransform: 399.999,104.7242,0,0,0,0,0,0,-118.11
L1 L3 = SMNR6045-6R8MT: Inductance:6.8uH Tolerance:±20% Tolerance:±20% Current Rating:- Current - Saturation(Isat):3.9A DC Resistance(DCR):40mΩ Type:Magnetic Shielded Inductor; Manufacturer: SXN(顺翔诺); AddInBom: yes; ModelId: 3e9401f539714e80815b88c2cc9596100819f05c4eef4c71ace90d822a990e87; ModelName: IND-SMD_L6.0-W6.0-H4.5_SMNR6045; ModelTransform: 236.22,236.22,0,90,0,0,0,0,0; Tolerance: ±20%; Current - Saturation(Isat): 3.9A; DC Resistance(DCR): 40mΩ
L2 = BLM21PG221SN1D: Impedance @ Frequency:220Ω@100MHz Tolerance:±25% Tolerance:±25% DC Resistance(DCR):45mΩ Current Rating:2A Number of Circuits:1 Operating Temperature:-55℃~+125℃ Operating Temperature:-55℃~+125℃; Manufacturer: muRata(村田); AddInBom: yes; ModelId: b83c7c5430874b8eb2319a65d94334290819f05c4eef4c71ace90d822a990e87; ModelName: R0805_L2.0-W1.3-H0.6; ModelTransform: 78.74,51.181,0,0,0,0,0,0.001,0; Tolerance: ±25%; DC Resistance(DCR): 45mΩ; Current Rating: 2A; Number of Circuits: 1
LED1 = NCD0603Y2: Lamp Holder Type:1.6mm x 0.8mm square LED Illumination Color:Yellow Voltage - Forward(Vf):1.6V~2.6V Voltage - Forward(Vf):1.6V~2.6V Power(Watts):65mW Test Current:25mA Wavelength - Dominant:586nm~595nm Wavelength - Dominant:586nm~595nm Peak Wavelength:595; Manufacturer: 国星光电; Symbol: FC-1608YXK-585F08; AddInBom: yes; ModelId: 5e3b568068dd46cf8019c1d1baa0031b0819f05c4eef4c71ace90d822a990e87; ModelTransform: 63.7794,32.283,0,0,0,0,0,0,0; Illumination Color: Yellow; Power(Watts): 65mW; Test Current: 25mA; Peak Wavelength: 595nm; Diode Configuration: Discrete Diode; Luminous Intensity: 220mcd; Viewing Angle: 130°; Half wave width: 15nm
LED2 LED3 = KT-0603G: Lamp Holder Type:1.6mm x 0.8mm square LED Illumination Color:Emerald Green Voltage - Forward(Vf):3.1V Voltage - Forward(Vf):3.1V Power(Watts):100mW Forward Current:5mA Wavelength - Dominant:513nm~528nm Wavelength - Dominant:513nm~528nm Peak Wavelength:525; Manufacturer: KENTO; Symbol: 0603 Green 509-620mcd; AddInBom: yes; ModelId: 5e3b568068dd46cf8019c1d1baa0031b0819f05c4eef4c71ace90d822a990e87; ModelTransform: 63.7794,32.283,0,0,0,0,0,0,0; Voltage - Forward(Vf): 3.1V; Power(Watts): 100mW; Forward Current: 5mA; Peak Wavelength: 525nm; Diode Configuration: Discrete Diode; Lens Color: Water Clear; Luminous Intensity: 430mcd; Viewing Angle: 120°
LED4 = KT-0603R: Lamp Holder Type:1.6mm x 0.8mm square LED Illumination Color:Red Voltage - Forward(Vf):1.8V~2.4V Voltage - Forward(Vf):1.8V~2.4V Power(Watts):40mW Forward Current:20mA Wavelength - Dominant:615nm~630nm Wavelength - Dominant:615nm~630nm Peak Wavelength:645; Manufacturer: KENTO; AddInBom: yes; ModelId: 19cc79473bbc420a8203ad67d1a57d420819f05c4eef4c71ace90d822a990e87; ModelName: LED0603_L1.6-W0.8-H0.6; ModelTransform: 63.7794,31.496,0,0,0,0,0,0,0; Illumination Color: Red; Power(Watts): 40mW; Forward Current: 20mA; Peak Wavelength: 645nm; Diode Configuration: Discrete Diode; Lens Color: Water Clear; Luminous Intensity: 300mcd; Viewing Angle: 120°
Q1 Q4-Q6 = AO3401A_C15127: Number:1 P-Channel Drain to Source Voltage:30V Current - Continuous Drain(Id):4A RDS(on):47mΩ@10V；85mΩ@2.5V；60mΩ@4.5V Pd - Power Dissipation:- Gate Threshold Voltage (Vgs(th)):900mV Gate Charge(Qg):14nC@10V Input Capacitance(Ciss):645pF Reverse Transfer C; Manufacturer: AOS; AddInBom: yes; ModelId: 62a57c6760504a01965db6419a6d07df0819f05c4eef4c71ace90d822a990e87; ModelName: SOT-23-3P_L2.9-W1.3-H1.0-LS2.4-P0.95; ModelTransform: 98.64468,114.173,0,180,0,0,0.001,-0.002,0; Drain to Source Voltage: 30V; Current - Continuous Drain(Id): 4A; Gate Threshold Voltage (Vgs(th)): 900mV; Input Capacitance(Ciss): 645pF; Reverse Transfer Capacitance (Crss@Vds): 55pF; Output Capacitance(Coss): 80pF
Q2 Q3 = 2N7002_C8545: Number:1 N-channel Drain to Source Voltage:60V Current - Continuous Drain(Id):115mA RDS(on):5Ω@10V Pd - Power Dissipation:225mW Gate Threshold Voltage (Vgs(th)):2.5V Gate Charge(Qg):- Input Capacitance(Ciss):50pF Reverse Transfer Capacitance (Crss@Vds):5p; Manufacturer: CJ(江苏长电/长晶); AddInBom: yes; ModelId: 62a57c6760504a01965db6419a6d07df0819f05c4eef4c71ace90d822a990e87; ModelName: SOT-23-3P_L2.9-W1.3-H1.0-LS2.4-P0.95; ModelTransform: 98.425,114.173,0,180,0,0,0.0005,-0.0005,0; Drain to Source Voltage: 60V; Current - Continuous Drain(Id): 115mA; RDS(on): 5Ω@10V; Pd - Power Dissipation: 225mW; Gate Threshold Voltage (Vgs(th)): 2.5V; Input Capacitance(Ciss): 50pF; Reverse Transfer Capacitance (Crss@Vds): 5pF; Output Capacitance(Coss): 25pF; Vgs: ±20V
R1 = RC0805FR-07910KL: Type:Thick Film Resistor Resistance:910kΩ Tolerance:±1% Tolerance:±1% Power(Watts):125mW Voltage-Supply(Max):150V Temperature Coefficient:±100ppm/℃ Temperature Coefficient:±100ppm/℃ Operating Temperature:-55℃~+155℃ Operating Temperature:-55℃~+155℃; Manufacturer: YAGEO(国巨); AddInBom: yes; ModelId: b83c7c5430874b8eb2319a65d94334290819f05c4eef4c71ace90d822a990e87; ModelName: R0805_L2.0-W1.3-H0.6; ModelTransform: 78.74,51.181,0,0,0,0,0,-0.0005,0; Tolerance: ±1%; Power(Watts): 125mW; Voltage-Supply(Max): 150V
R2 R3 R9-R11 R18 = 0805W8F1003T5E: Type:Thick Film Resistor Resistance:100kΩ Tolerance:±1% Tolerance:±1% Power(Watts):125mW Voltage-Supply(Max):150V Temperature Coefficient:±100ppm/℃ Temperature Coefficient:±100ppm/℃ Operating Temperature:-55℃~+155℃ Operating Temperature:-55℃~+155℃; Manufacturer: UNI-ROYAL(厚声); Symbol: 0805W8F1003T5E_C149504; AddInBom: yes; ModelId: b83c7c5430874b8eb2319a65d94334290819f05c4eef4c71ace90d822a990e87; ModelName: R0805_L2.0-W1.3-H0.6; ModelTransform: 78.74,51.181,0,0,0,0,0,-0.0005,0; Tolerance: ±1%; Power(Watts): 125mW; Voltage-Supply(Max): 150V
R4 R5 = 0805W8F5101T5E: Type:Thick Film Resistor Resistance:5.1kΩ Tolerance:±1% Tolerance:±1% Power(Watts):125mW Voltage-Supply(Max):150V Temperature Coefficient:±100ppm/℃ Temperature Coefficient:±100ppm/℃ Operating Temperature:-55℃~+155℃ Operating Temperature:-55℃~+155℃; Manufacturer: UNI-ROYAL(厚声); Add into BOM: no; ConvertToPcb: yes; ModelId: b83c7c5430874b8eb2319a65d94334290819f05c4eef4c71ace90d822a990e87; ModelName: R0805_L2.0-W1.3-H0.6; ModelTransform: 78.74,51.181,0,0,0,0,0,-0.0005,0; Tolerance: ±1%; Power(Watts): 125mW; Voltage-Supply(Max): 150V
R6 R26 R31 = 0805W8F0000T5E_C17477: Type:Thick Film Resistor Resistance:0Ω Tolerance:±1% Tolerance:±1% Power(Watts):125mW Voltage-Supply(Max):150V Temperature Coefficient:±800ppm/℃ Temperature Coefficient:±800ppm/℃ Operating Temperature:-55℃~+155℃ Operating Temperature:-55℃~+155℃; Manufacturer: UNI-ROYAL(厚声); AddInBom: yes; ModelId: b83c7c5430874b8eb2319a65d94334290819f05c4eef4c71ace90d822a990e87; ModelName: R0805_L2.0-W1.3-H0.6; ModelTransform: 78.74,51.181,0,0,0,0,0,-0.0005,0; Tolerance: ±1%; Power(Watts): 125mW; Voltage-Supply(Max): 150V
R7 = 0805W8F1003T5E: Type:Thick Film Resistor Resistance:100kΩ Tolerance:±1% Tolerance:±1% Power(Watts):125mW Voltage-Supply(Max):150V Temperature Coefficient:±100ppm/℃ Temperature Coefficient:±100ppm/℃ Operating Temperature:-55℃~+155℃ Operating Temperature:-55℃~+155℃; Manufacturer: UNI-ROYAL(厚声); Symbol: 0805W8F1003T5E_C149504; Add into BOM: no; ConvertToPcb: yes; ModelId: b83c7c5430874b8eb2319a65d94334290819f05c4eef4c71ace90d822a990e87; ModelName: R0805_L2.0-W1.3-H0.6; ModelTransform: 78.74,51.181,0,0,0,0,0,-0.0005,0; Tolerance: ±1%; Power(Watts): 125mW; Voltage-Supply(Max): 150V
R8 R14 = 0805W8F1002T5E: Type:Thick Film Resistor Resistance:10kΩ Tolerance:±1% Tolerance:±1% Power(Watts):125mW Voltage-Supply(Max):150V Temperature Coefficient:±100ppm/℃ Temperature Coefficient:±100ppm/℃ Operating Temperature:-55℃~+155℃ Operating Temperature:-55℃~+155℃; Manufacturer: UNI-ROYAL(厚声); AddInBom: yes; ModelId: b83c7c5430874b8eb2319a65d94334290819f05c4eef4c71ace90d822a990e87; ModelName: R0805_L2.0-W1.3-H0.6; ModelTransform: 78.74,51.181,0,0,0,0,0,-0.0005,0; Tolerance: ±1%; Power(Watts): 125mW; Voltage-Supply(Max): 150V
R12 R15 R16 R19 R29 = 0805W8F1001T5E: Type:Thick Film Resistors Resistance:1kΩ Tolerance:±1% Tolerance:±1% Power(Watts): Overload Voltage (Max): Temperature Coefficient:±100ppm/℃ Temperature Coefficient:±100ppm/℃ Operating Temperature Range:-55℃~+155℃ Operating Temperature Range:-55℃~+155℃; Manufacturer: UNI-ROYAL(厚声); AddInBom: yes; ModelId: b83c7c5430874b8eb2319a65d94334290819f05c4eef4c71ace90d822a990e87; ModelName: R0805_L2.0-W1.3-H0.6; ModelTransform: 78.74,51.181,0,0,0,0,0,-0.0005,0; Tolerance: ±1%
R13 = 0805W8F2001T5E: Type:Thick Film Resistor Resistance:2kΩ Tolerance:±1% Tolerance:±1% Power(Watts):125mW Voltage-Supply(Max):150V Temperature Coefficient:±100ppm/℃ Temperature Coefficient:±100ppm/℃ Operating Temperature:-55℃~+155℃ Operating Temperature:-55℃~+155℃; Manufacturer: UNI-ROYAL(厚声); AddInBom: yes; ModelId: b83c7c5430874b8eb2319a65d94334290819f05c4eef4c71ace90d822a990e87; ModelName: R0805_L2.0-W1.3-H0.6; ModelTransform: 78.74,51.181,0,0,0,0,0,-0.0005,0; Tolerance: ±1%; Power(Watts): 125mW; Voltage-Supply(Max): 150V
R17 = RE1206F1R050: Type:Current Sense Resistor；Alloy Resistor Resistance:50mΩ Tolerance:±1% Tolerance:±1% Power(Watts):1W Temperature Coefficient:±50ppm/℃ Temperature Coefficient:±50ppm/℃; Manufacturer: JIERR(捷而瑞); AddInBom: yes; ModelId: 04f48aacb8114155959811d2338bbb060819f05c4eef4c71ace90d822a990e87; ModelName: R1206_L3.2-W1.6-H0.6; ModelTransform: 125.984,62.992,0,0,0,0,0,0,0; Tolerance: ±1%; Power(Watts): 1W
R20 R27 R28 = 0805W8F0000T5E_C17477: Type:Thick Film Resistor Resistance:0Ω Tolerance:±1% Tolerance:±1% Power(Watts):125mW Voltage-Supply(Max):150V Temperature Coefficient:±800ppm/℃ Temperature Coefficient:±800ppm/℃ Operating Temperature:-55℃~+155℃ Operating Temperature:-55℃~+155℃; Manufacturer: UNI-ROYAL(厚声); Add into BOM: no; ConvertToPcb: yes; ModelId: b83c7c5430874b8eb2319a65d94334290819f05c4eef4c71ace90d822a990e87; ModelName: R0805_L2.0-W1.3-H0.6; ModelTransform: 78.74,51.181,0,0,0,0,0,-0.0005,0; Tolerance: ±1%; Power(Watts): 125mW; Voltage-Supply(Max): 150V
R21 = 0805W8F7502T5E: Type:Thick Film Resistor Resistance:75kΩ Tolerance:±1% Tolerance:±1% Power(Watts):125mW Voltage-Supply(Max):150V Temperature Coefficient:±100ppm/℃ Temperature Coefficient:±100ppm/℃ Operating Temperature:-55℃~+155℃ Operating Temperature:-55℃~+155℃; Manufacturer: UNI-ROYAL(厚声); AddInBom: yes; ModelId: b83c7c5430874b8eb2319a65d94334290819f05c4eef4c71ace90d822a990e87; ModelName: R0805_L2.0-W1.3-H0.6; ModelTransform: 78.74,51.181,0,0,0,0,0,-0.0005,0; Tolerance: ±1%; Power(Watts): 125mW; Voltage-Supply(Max): 150V
R22 R23 = 0805W8F1002T5E: Type:Thick Film Resistor Resistance:10kΩ Tolerance:±1% Tolerance:±1% Power(Watts):125mW Voltage-Supply(Max):150V Temperature Coefficient:±100ppm/℃ Temperature Coefficient:±100ppm/℃ Operating Temperature:-55℃~+155℃ Operating Temperature:-55℃~+155℃; Manufacturer: UNI-ROYAL(厚声); Add into BOM: yes; 3D Model: b83c7c5430874b8eb2319a65d94334290819f05c4eef4c71ace90d822a990e87; 3D Model Transform: 78.74,51.181,0,0,0,0,0,-0.0005,0; Tolerance: ±1%; Power(Watts): 125mW; Voltage-Supply(Max): 150V; ModelName: R0805_L2.0-W1.3-H0.6
R24 R25 = 0805W8F1002T5E: Type:Thick Film Resistor Resistance:10kΩ Tolerance:±1% Tolerance:±1% Power(Watts):125mW Voltage-Supply(Max):150V Temperature Coefficient:±100ppm/℃ Temperature Coefficient:±100ppm/℃ Operating Temperature:-55℃~+155℃ Operating Temperature:-55℃~+155℃; Manufacturer: UNI-ROYAL(厚声); Add into BOM: no; ConvertToPcb: yes; ModelId: b83c7c5430874b8eb2319a65d94334290819f05c4eef4c71ace90d822a990e87; ModelName: R0805_L2.0-W1.3-H0.6; ModelTransform: 78.74,51.181,0,0,0,0,0,-0.0005,0; Tolerance: ±1%; Power(Watts): 125mW; Voltage-Supply(Max): 150V
R30 = 0805W8F1200T5E: Type:Thick Film Resistor Resistance:120Ω Tolerance:±1% Tolerance:±1% Power(Watts):125mW Voltage-Supply(Max):150V Temperature Coefficient:±100ppm/℃ Temperature Coefficient:±100ppm/℃ Operating Temperature:-55℃~+155℃ Operating Temperature:-55℃~+155℃; Manufacturer: UNI-ROYAL(厚声); Add into BOM: no; ConvertToPcb: yes; ModelId: b83c7c5430874b8eb2319a65d94334290819f05c4eef4c71ace90d822a990e87; ModelName: R0805_L2.0-W1.3-H0.6; ModelTransform: 78.74,51.181,0,0,0,0,0,-0.0005,0; Tolerance: ±1%; Power(Watts): 125mW; Voltage-Supply(Max): 150V
R32 = 0805W8F1002T5E: Type:Thick Film Resistor Resistance:10kΩ Tolerance:±1% Tolerance:±1% Power(Watts):125mW Voltage-Supply(Max):150V Temperature Coefficient:±100ppm/℃ Temperature Coefficient:±100ppm/℃ Operating Temperature:-55℃~+155℃ Operating Temperature:-55℃~+155℃; Manufacturer: UNI-ROYAL(厚声); Add into BOM: yes; ModelId: b83c7c5430874b8eb2319a65d94334290819f05c4eef4c71ace90d822a990e87; ModelName: R0805_L2.0-W1.3-H0.6; ModelTransform: 78.74,51.181,0,0,0,0,0,-0.0005,0; Tolerance: ±1%; Power(Watts): 125mW; Voltage-Supply(Max): 150V
R33 R34 = 0805W8F5600T5E: Type:Thick Film Resistors Resistance: Tolerance:±1% Tolerance:±1% Power(Watts): Overload Voltage (Max): Temperature Coefficient:±100ppm/℃ Temperature Coefficient:±100ppm/℃ Operating Temperature Range:-55℃~+155℃ Operating Temperature Range:-55℃~+155℃; Manufacturer: UNI-ROYAL(厚声); AddInBom: yes; ModelId: b83c7c5430874b8eb2319a65d94334290819f05c4eef4c71ace90d822a990e87; ModelName: R0805_L2.0-W1.3-H0.6; ModelTransform: 78.74,51.181,0,0,0,0,0,-0.0005,0; Tolerance: ±1%
SCREW1-SCREW4 = Screw-Hole-M4: ConvertToPcb: yes
U1 = AP63205WU-7: Function:Step-down type Voltage - Supply:3.8V~32V Voltage - Supply:3.8V~32V Output Voltage:5V Output Voltage:5V Output Current:2A Frequency - Switching:1.1MHz Frequency - Switching:1.1MHz Operating Temperature:-40℃~+85℃@(TA) Operating Temperature:-40℃~+85; Manufacturer: DIODES(美台); AddInBom: yes; ModelId: b82f856f33de448a91344795012188a20819f05c4eef4c71ace90d822a990e87; ModelName: TSOT-23-6_L2.9-W1.6-H1.1-LS2.8-P0.95; ModelTransform: 110.236,114.173,0,90,0,0,0,0,0; Output Voltage: 5V; Output Current: 2A; Frequency - Switching: 1.1MHz; Number of Outputs: 1; Topology: Buck; Quiescent Current: 22uA; Switch tube (built-in/external): Built-in; Output Type: Fixed
U2 = TPS2041BDBVR: Type:High Side Switch Number of Channels:1 Control Input Logic:Active Low Voltage - Supply:2.7V~5.5V Voltage - Supply:2.7V~5.5V Maximum Continuous Current:500mA RDS(on):95mΩ Features:Short-Circuit  Protection；Overcurrent Protection；Over temperature protec; Manufacturer: TI(德州仪器); AddInBom: yes; ModelId: 3168b22659ce4998ae232d44bb704e0a0819f05c4eef4c71ace90d822a990e87; ModelName: SOT-23-5_L2.9-W1.6-H1.1-LS2.8-P0.95; ModelTransform: 114.173,109.636,0,180,0,0,0,0,0; Number of Channels: 1; Maximum Continuous Current: 500mA; RDS(on): 95mΩ
U3 = TP4056-42-ESOP8: The Chip Type:Charging IC Voltage - Supply:4V~8V Voltage - Supply:4V~8V Charge Current - Max:1A Charging Saturation Voltage:4.2V End-Off Voltage:- Type of Battery:Lithium Battery Number of Cells:1 Number of Cells:1 Operating Temperature:-40℃~+85℃ Operatin; Manufacturer: TOPPOWER(南京拓微); Symbol: TP4056_1; AddInBom: yes; ModelId: 7028148f6b924eec86ae6696b4a125a20819f05c4eef4c71ace90d822a990e87; ModelName: ESOP-8_L4.9-W3.9-H1.6-LS6.0-P1.27; ModelTransform: 240.157,192.913,0,90,0,0,0,0,0; Voltage - Supply: 4V~8V; Charge Current - Max: 1A; Charging Saturation Voltage: 4.2V; Number of Cells: 1; Battery Temperature Detection: Support; Supply Current (Iq): 2uA
U5 = INA219AIDR: Number of Channels:1 Vcm - Common Mode Voltage:0V~26V Vcm - Common Mode Voltage:0V~26V Gain:- Bandwidth:- Ib - Input Bias Current:20nA Vos - Input Offset Voltage:10uV Operating Temperature:-40℃~+125℃ Operating Temperature:-40℃~+125℃ Differential Voltage:±; Manufacturer: TI(德州仪器); AddInBom: yes; ModelId: 2ec1ac1bf9bf4d09a988fcee15e6a02d0819f05c4eef4c71ace90d822a990e87; ModelName: SOIC-8_L4.9-W3.9-H1.7-LS6.0-P1.27; ModelTransform: 192.913,236.22,0,0,0,0,0,0,0; Number of Channels: 1; Vcm - Common Mode Voltage: 0V~26V; Ib - Input Bias Current: 20nA; Vos - Input Offset Voltage: 10uV; Differential Voltage: ±26V; Single Supply: 3V~5.5V; Quiescent Current: 700uA; Input Offset Voltage Drift(Vos TC): 0.1uV/℃; Common Mode Rejection Ratio (CMRR): 120dB
U6 = AP2112K-3.3TRG1: Output Configuration:Positive Voltage - Supply:6V Output Voltage:3.3V Output Voltage:3.3V Output Current:600mA Power Supply Rejection Ratio (PSRR):65dB@(1kHz) Voltage Dropout:250mV@(600mA) standby current:55uA Noise:50uVrms Features:Enable control；Short C; Manufacturer: DIODES(美台); AddInBom: yes; ModelId: 6177bbcd6fc94df4b4ba2f22405723a00819f05c4eef4c71ace90d822a990e87; ModelTransform: 114.173,110.236,0,0,0,0,0,0,0; Voltage - Supply: 6V; Output Voltage: 3.3V; standby current: 55uA; Output Type: Fixed; Number of Outputs: 1
U8 = TUSB320LAIRWBR: Manufacturer: TI(德州仪器); AddInBom: yes; ModelId: 6371d347ee444226803e1bf09a8fec1d0819f05c4eef4c71ace90d822a990e87; ModelName: X2QFN-12_L1.6-W1.6-H0.4-P0.40-TL; ModelTransform: 62.992,62.992,0,0,0,0,0,0,0
U9 = MT3608: Function:Boost Voltage - Supply:2V~24V Voltage - Supply:2V~24V Output Voltage:600mV~28V Output Voltage:600mV~28V Output Current:2A Frequency - Switching:1.2MHz Frequency - Switching:1.2MHz Operating Temperature:-40℃~+85℃ Operating Temperature:-40℃~+85℃ Sy; Manufacturer: 西安航天民芯; AddInBom: yes; ModelId: 1370be37a17e44418ae52e2b4cc1f5e50819f05c4eef4c71ace90d822a990e87; ModelName: SOT-23-6_L2.9-W1.6-H1.5-LS2.8-P0.95; ModelTransform: 110.236,113.364,0,90,0,0,0.0005,0.0005,0; Function: Boost; Voltage - Supply: 2V~24V; Output Current: 2A; Frequency - Switching: 1.2MHz; Synchronous Rectifier: No; Number of Outputs: 1; Quiescent Current: 100uA；1.6mA; Switch tube (built-in/external): Built-in; Output Type: Adjustable
USBC1 USBC2 = TYPE-C-31-M-12: Connector Type:Type-C Protocol Standard:- Gender:Female Mounting Type:Surface Mount, Right Angle Number of Contacts:16P Number of Ports:1 Current Rating-Power:5A Voltage Rating:20V Connect-Disconnect Life:10,000 cycles Length:7.35mm Operating Temperature:; Manufacturer: 韩国韩荣; AddInBom: yes; ModelId: 8421221a464047838322348b3a9debc30819f05c4eef4c71ace90d822a990e87; ModelTransform: 351.9678,311.023,0,180,0,0,0,-43.307,-33.465; Connector Type: Type-C; Gender: Female; Number of Contacts: 16P; Number of Ports: 1; Current Rating-Power: 5A; Voltage Rating: 20V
